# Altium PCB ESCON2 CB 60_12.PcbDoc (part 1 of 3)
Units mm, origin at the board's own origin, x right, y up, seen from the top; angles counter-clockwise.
Board outline 65.5 x 41 mm, 8 copper layers (Top Side, Mid Layer 1, Mid Layer 2, Mid Layer 3, Mid Layer 4, Mid Layer 5, Mid Layer 6, Bottom Side), stack 1.555 mm thick; 142 components, 77 nets, 455 pads, 2194 vias.
Unrouted connection lines stored in the file: 71.
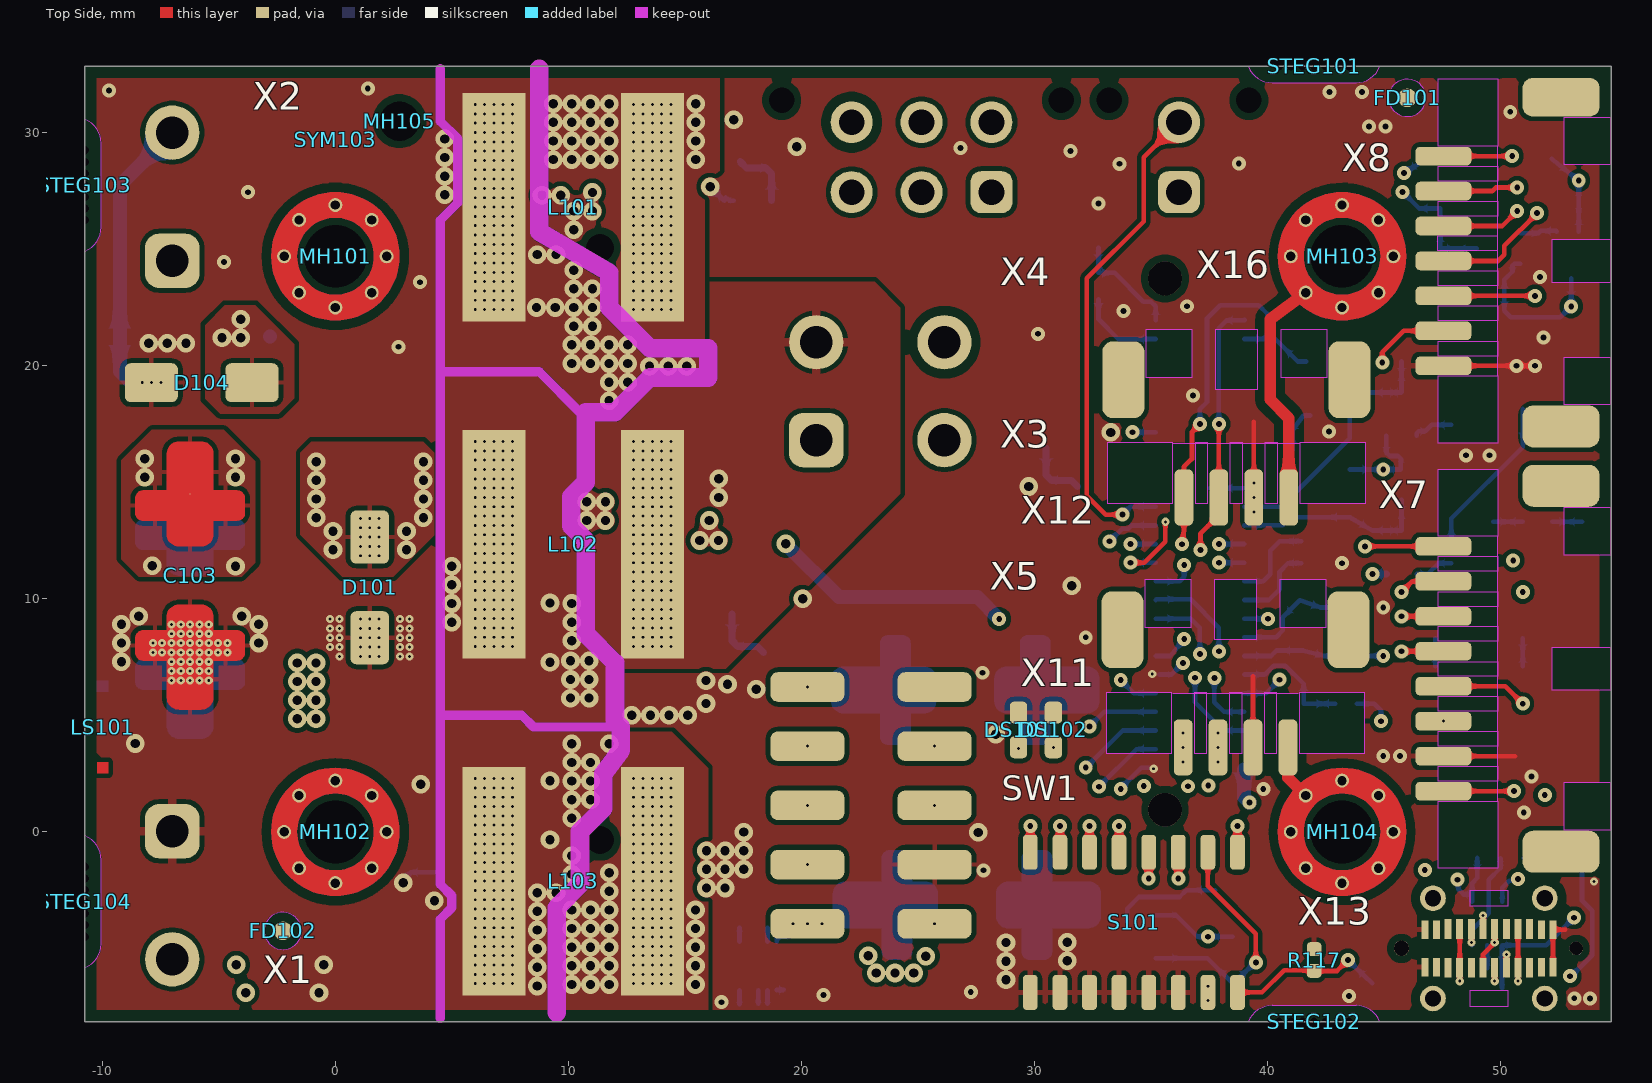
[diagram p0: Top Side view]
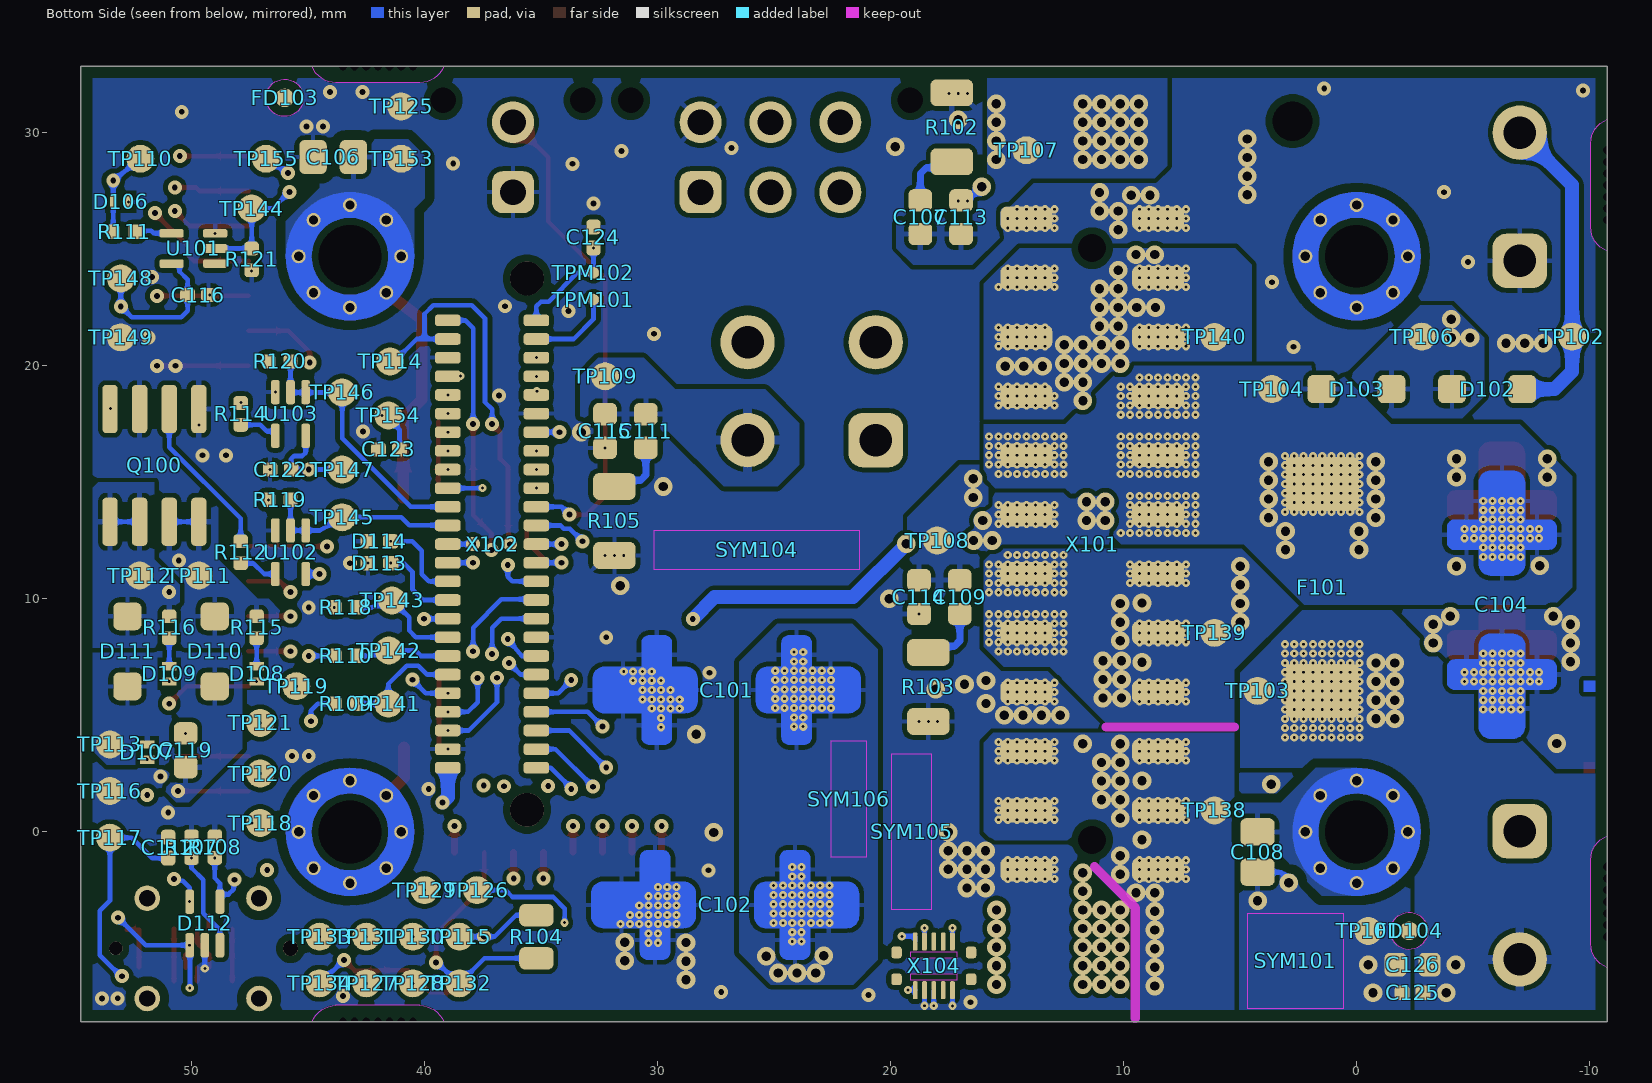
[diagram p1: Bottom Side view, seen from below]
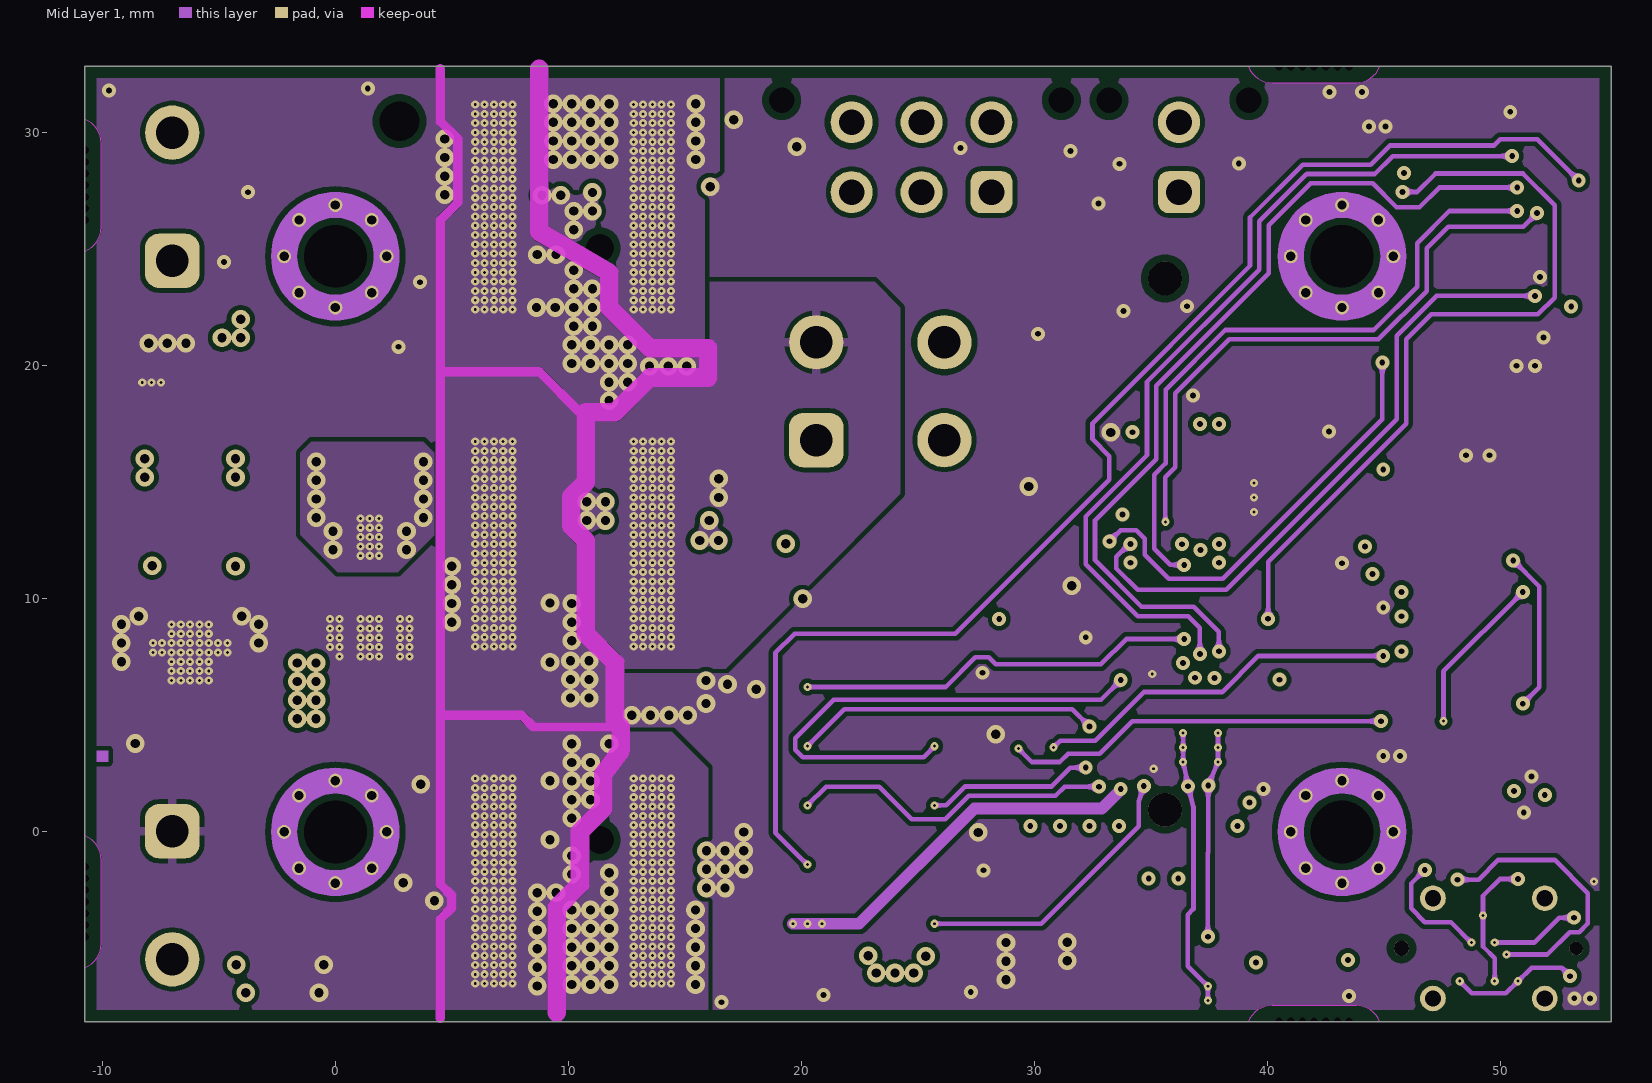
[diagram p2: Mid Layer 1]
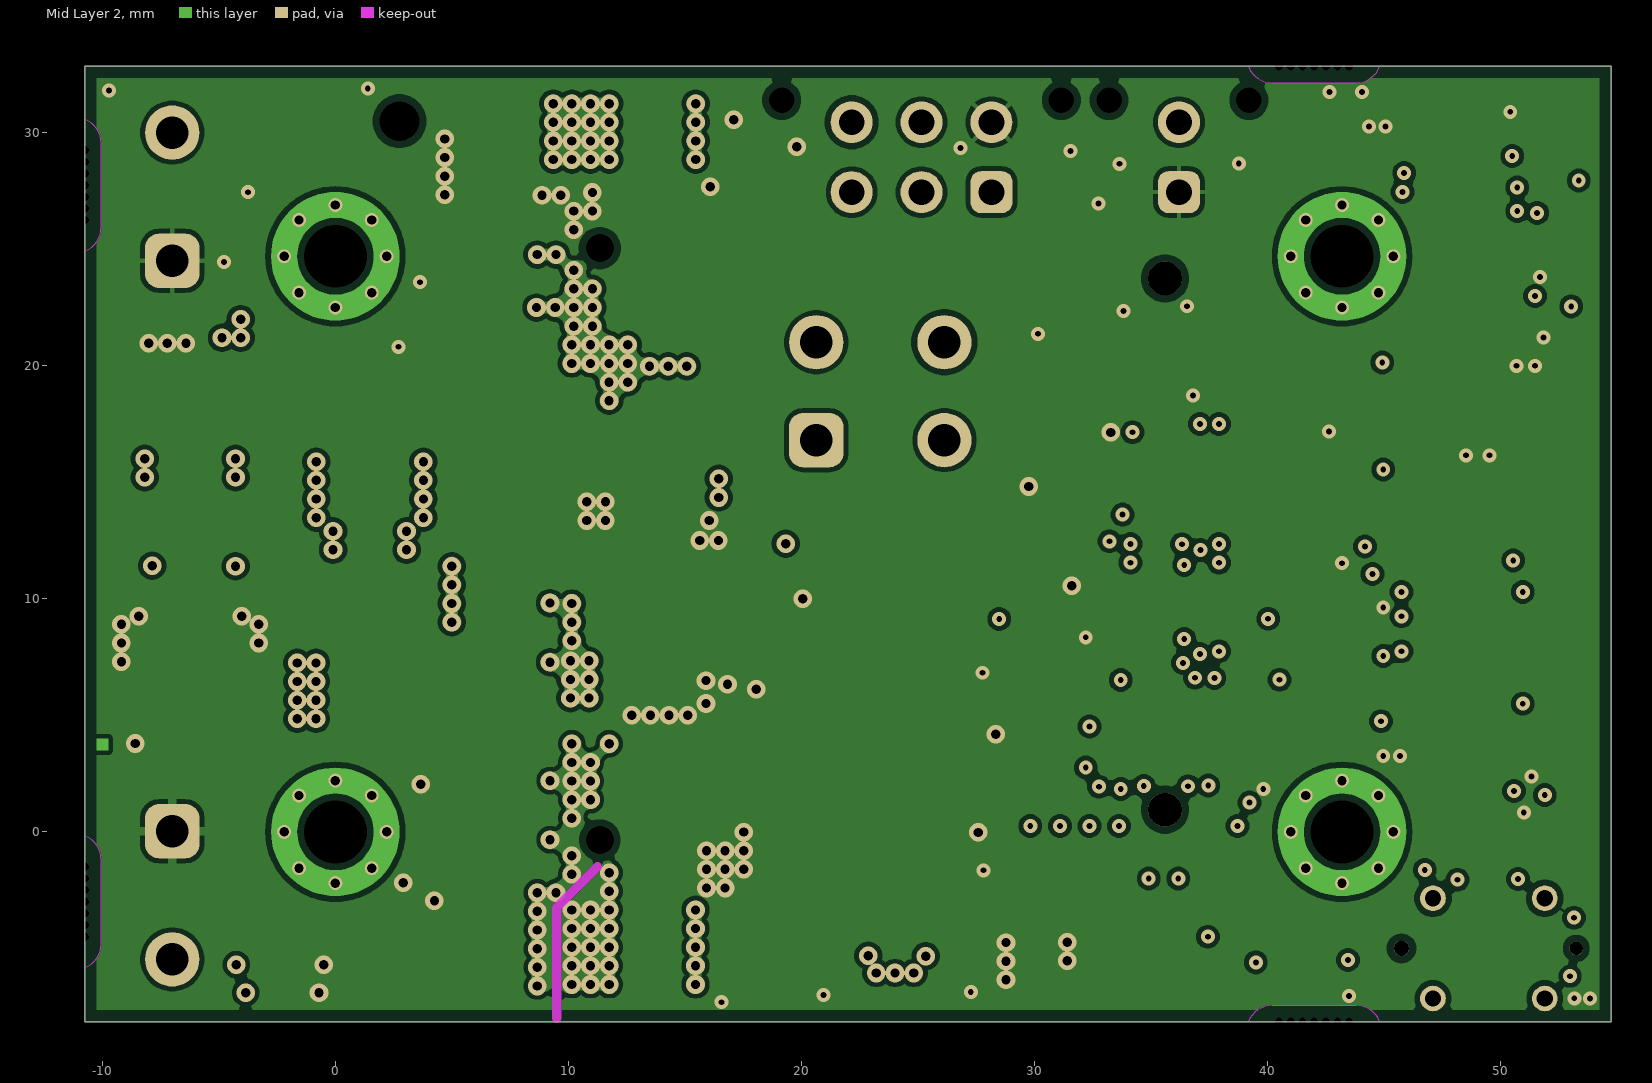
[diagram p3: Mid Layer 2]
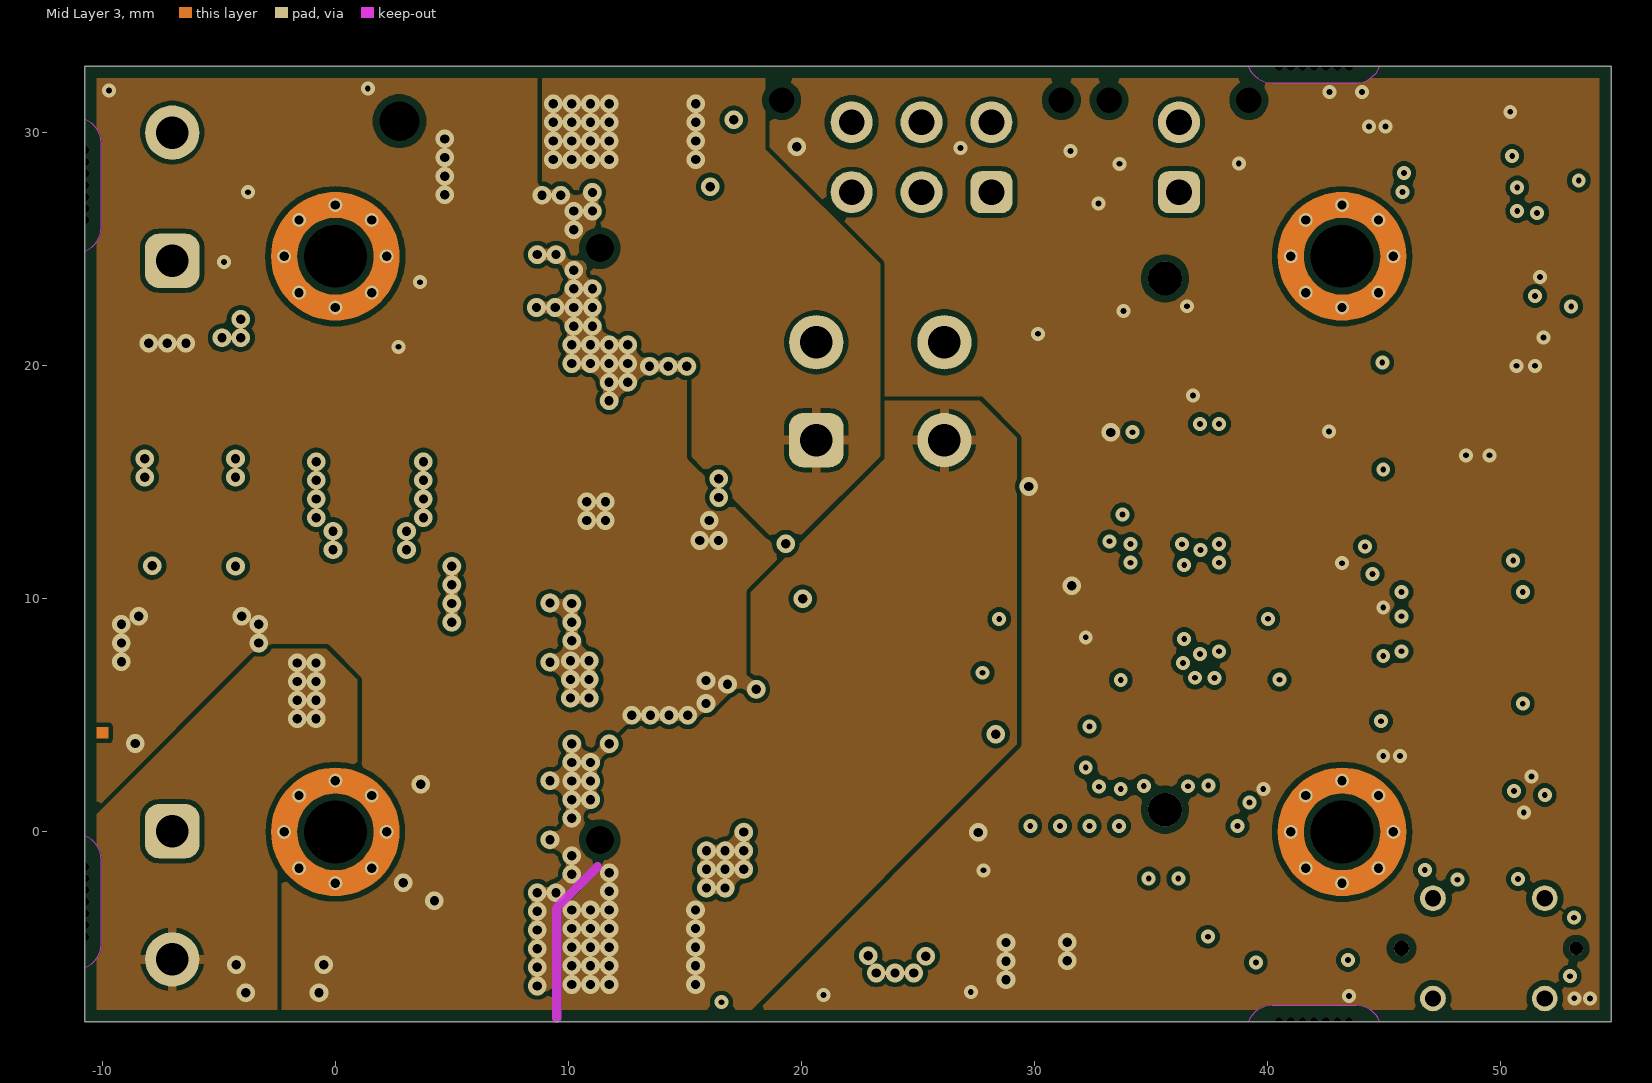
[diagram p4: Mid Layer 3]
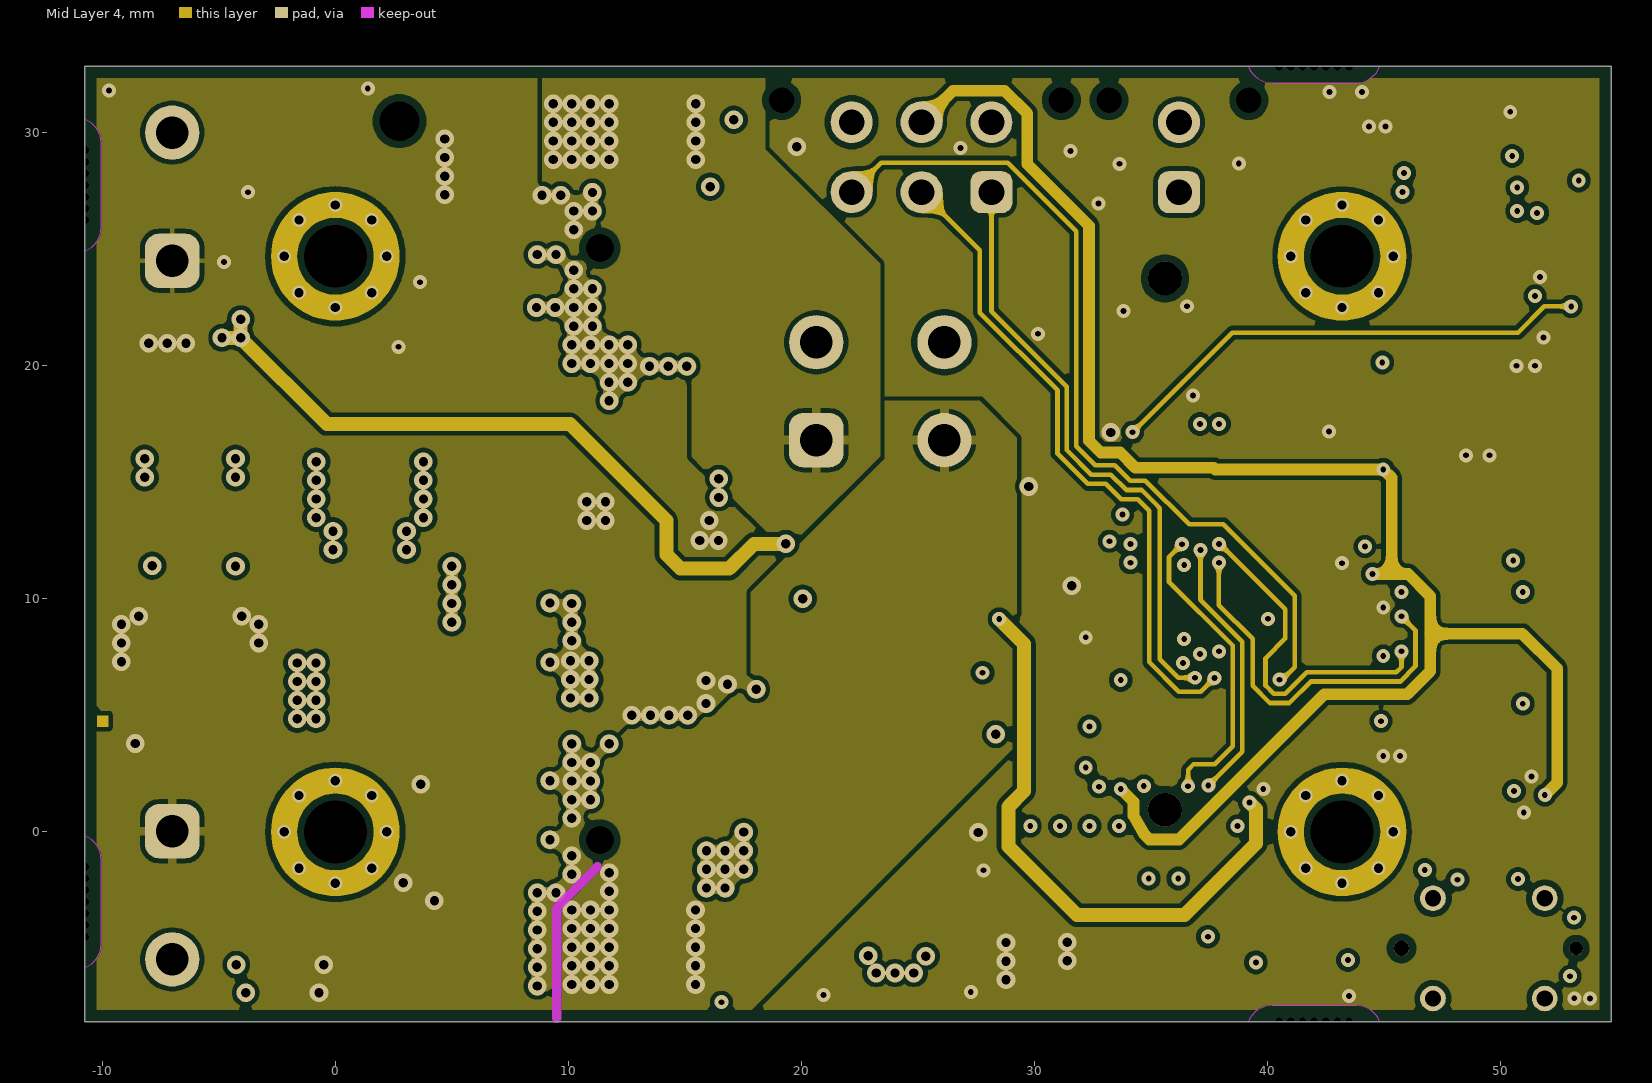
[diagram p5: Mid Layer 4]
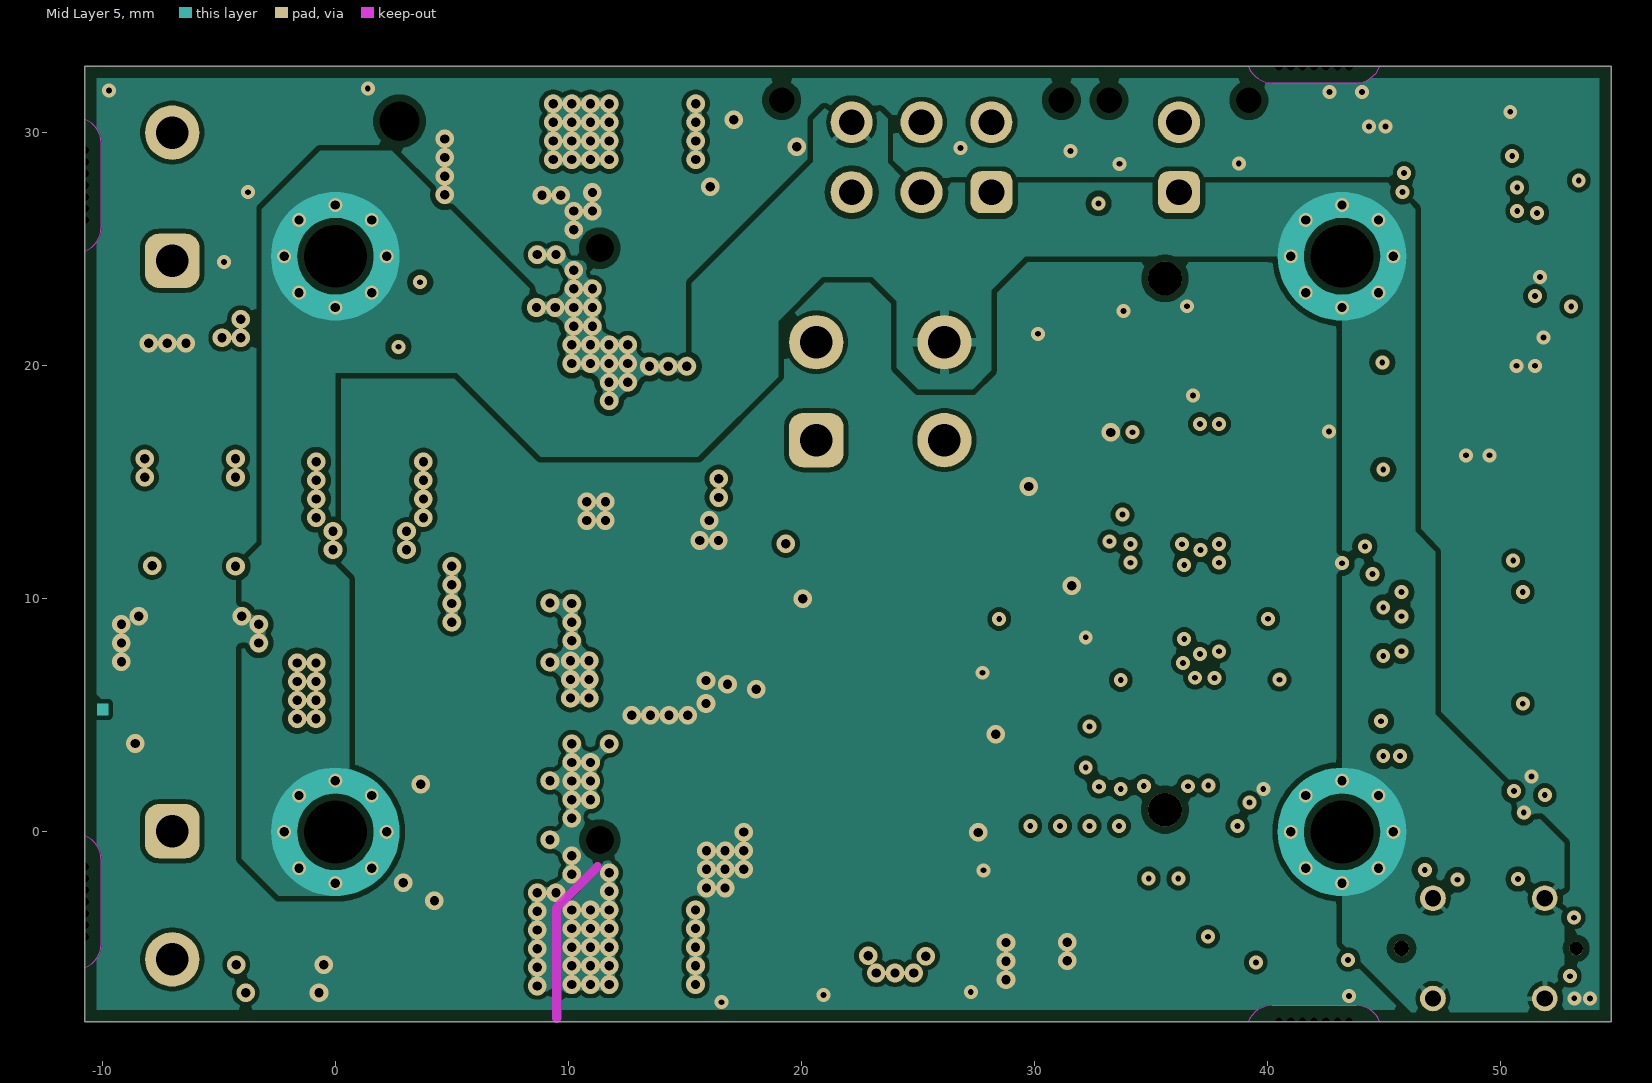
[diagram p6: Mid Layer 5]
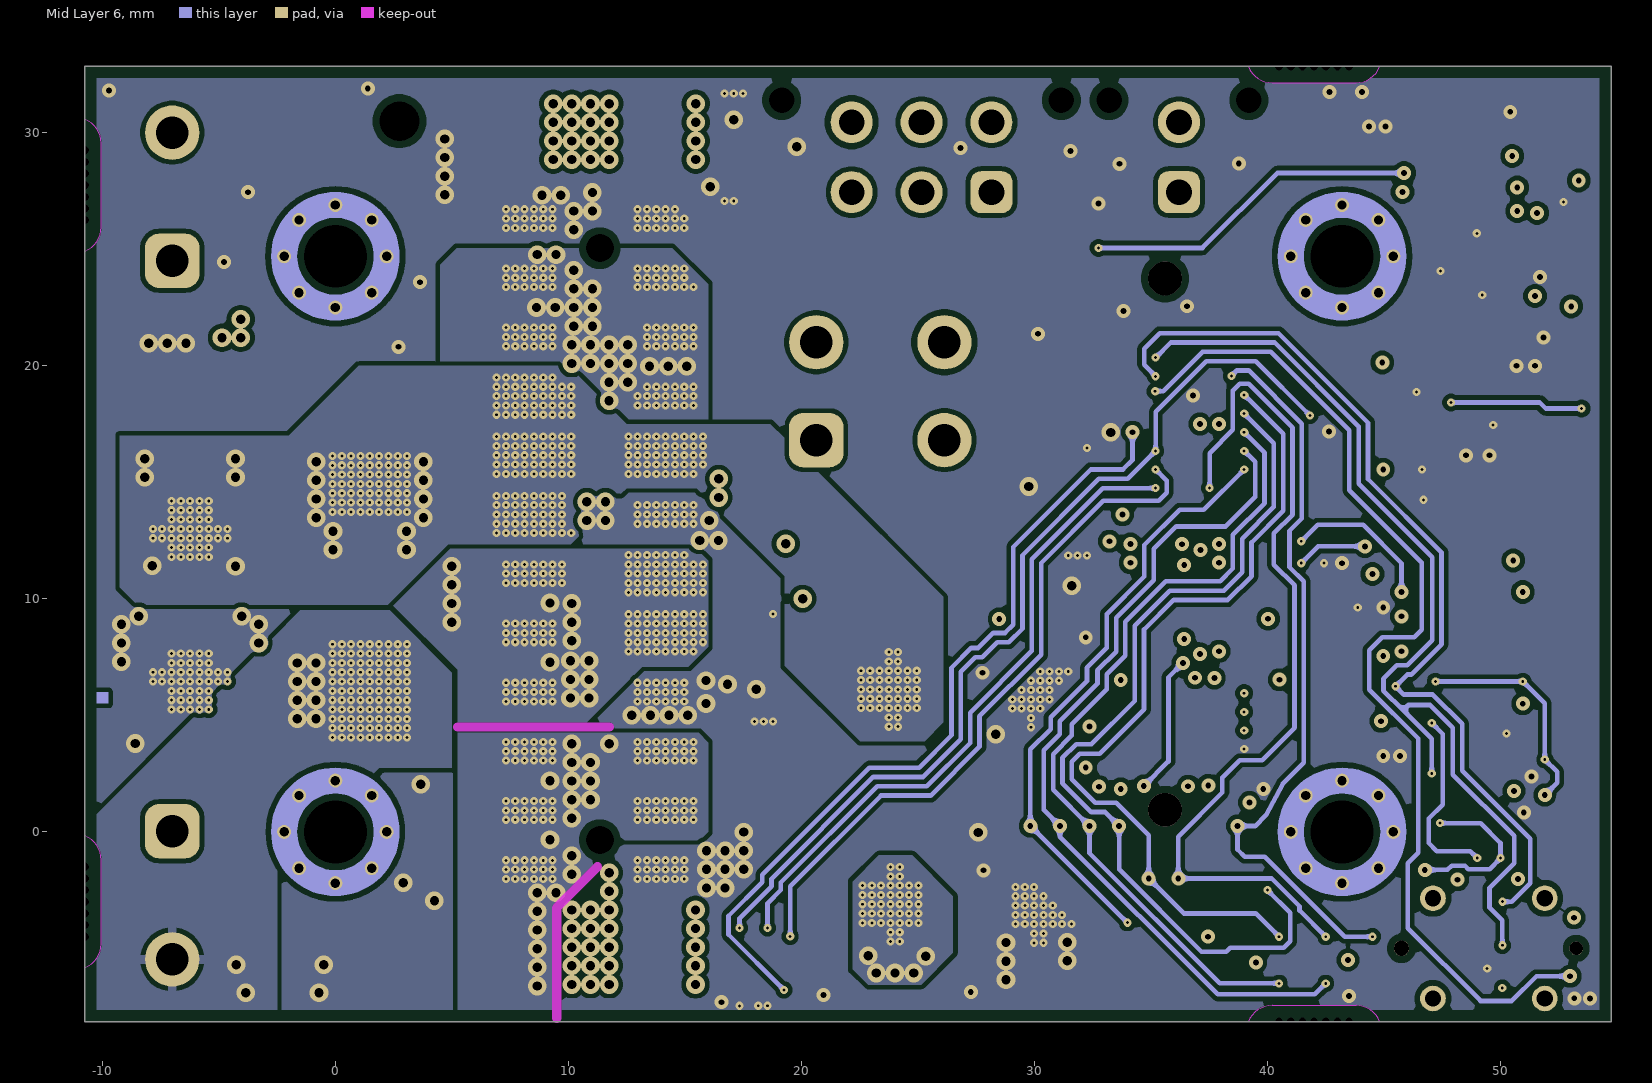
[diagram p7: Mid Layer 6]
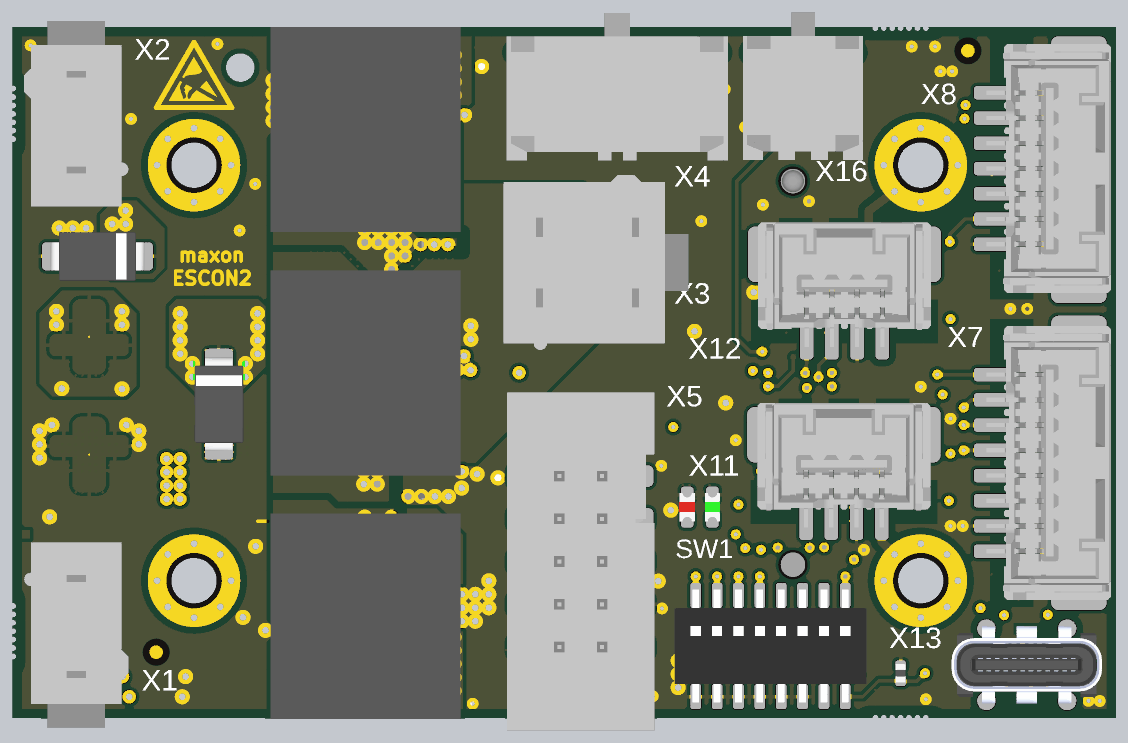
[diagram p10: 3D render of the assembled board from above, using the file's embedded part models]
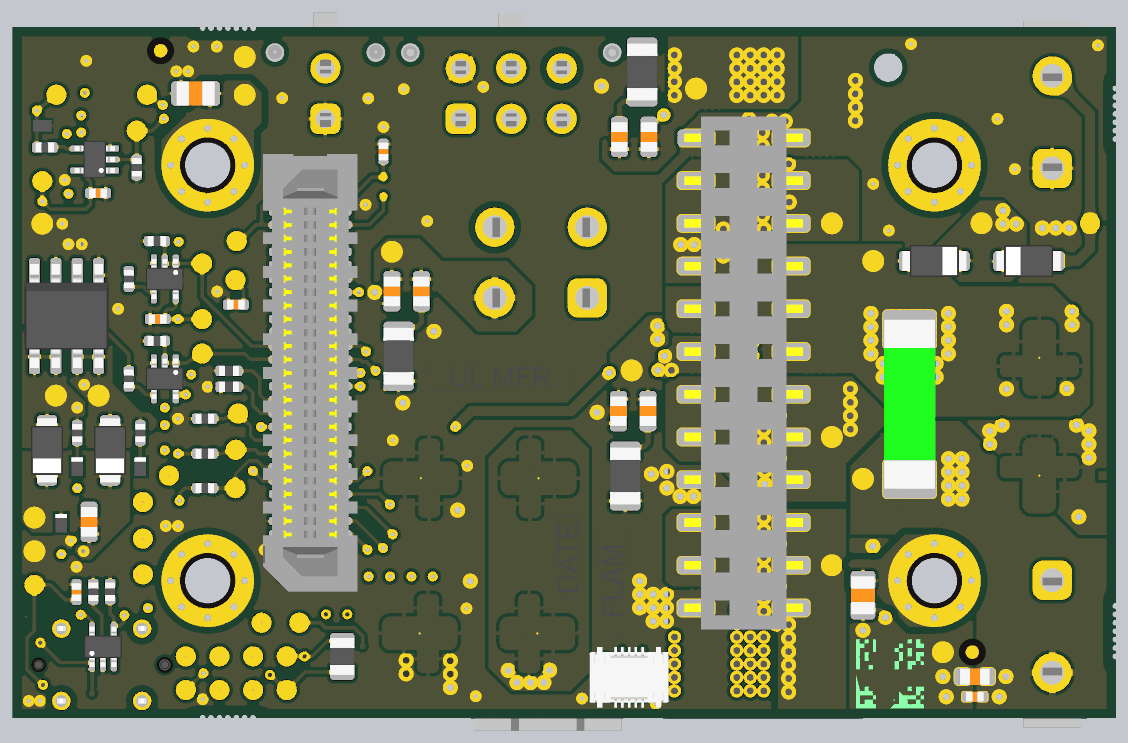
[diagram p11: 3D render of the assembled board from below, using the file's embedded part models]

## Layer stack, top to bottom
Top Solder: solder mask 0.015, Dk 3.5
Top Side: signal copper 0.03
Dielectric 1: prepreg 0.065, Dk 3.5
Mid Layer 1: signal copper 0.035
Core 1: core 0.3, Dk 4.5
Mid Layer 2: signal copper 0.035
Dielectric 2: prepreg 0.125, Dk 3.7
Mid Layer 3: signal copper 0.035
Core 2: core 0.3, Dk 4.5
Mid Layer 4: signal copper 0.035
Dielectric 3: prepreg 0.125, Dk 3.7
Mid Layer 5: signal copper 0.035
Core 3: core 0.3, Dk 4.5
Mid Layer 6: signal copper 0.035
Dielectric 4: prepreg 0.065, Dk 3.5
Bottom Side: signal copper 0.035
Bottom Solder: solder mask 0.015, Dk 3.5

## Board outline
-10.75,-8.15 54.75,-8.15 54.75,32.85 -10.75,32.85

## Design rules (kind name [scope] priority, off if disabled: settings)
AssemblyTestPointUsage [All] p1: valid=2
AssemblyTestpoint [All] p1: testpointundercomponent=TRUE minsize=1 maxsize=2 preferedsize=1.2 minholesize=0 maxholesize=0 preferedholesize=0 testpointgrid=0.05 usegrid=FALSE gridoriginx=120 gridoriginy=100 gridtolerance=0 allowsidebottom=TRUE minspacing=2 padholecenterclearance=0.6
BoardOutlineClearance BOC_AlignHole [InComponent('MH105')] p1: gap=0 ignorepadtopadclearanceinfootprint=FALSE
BoardOutlineClearance BOC_Overlay [OnLayer('Top Designator') OR OnLayer('Bottom Designator')] p2: gap=0 ignorepadtopadclearanceinfootprint=FALSE
BoardOutlineClearance BOC_Text [isText] p3: gap=0 ignorepadtopadclearanceinfootprint=FALSE
BoardOutlineClearance BOC_Fiducials [InComponent('FD*')] p4: gap=0.1 ignorepadtopadclearanceinfootprint=FALSE
BoardOutlineClearance BOC_Steg [InComponent('STEG*')] p5: gap=0 ignorepadtopadclearanceinfootprint=FALSE
BoardOutlineClearance BOC_Keepout [IsKeepout] p6: gap=0 ignorepadtopadclearanceinfootprint=FALSE
BoardOutlineClearance BOC_SGND [InNet('SGND')] p7: gap=0.4 ignorepadtopadclearanceinfootprint=FALSE
BoardOutlineClearance BOC_All [All] p8: gap=0.5 ignorepadtopadclearanceinfootprint=FALSE
Clearance C_NPTHtoAll [(ObjectKind = 'Pad') AND (Layer = 'MultiLayer') AND (PadIsPlated = 'False') AND NOT HasFootprint('Steg*')] p1: gap=0.3 ignorepadtopadclearanceinfootprint=FALSE except(0.298: SMDPad-THPad SMDPad-Fill SMDPad-Poly SMDPad-Region SMDPad-Hole THPad-Fill THPad-Poly THPad-Region Fill-Hole Poly-Hole Region-Hole)
Clearance C_LStoAll [InComponent('LS*')] p2: gap=0.2 ignorepadtopadclearanceinfootprint=FALSE
Clearance C_IsKeepout [IsKeepOut] p3: gap=0 ignorepadtopadclearanceinfootprint=FALSE
Clearance C_NetSGNDtoAll_onOutside [InNet('SGND') AND ( ExistsOnLayer('Top Side') OR ExistsOnLayer('Bottom Side') ) vs (ExistsOnLayer('Top Side') OR ExistsOnLayer('Bottom Side') ) AND NOT IsKeepOut] p4: gap=0.4 ignorepadtopadclearanceinfootprint=FALSE
Clearance C_NetSGNDtoAll_onMid [InNet('SGND') AND ( ExistsOnLayer('Mid Layer 1') OR ExistsOnLayer('Mid Layer 2') OR ExistsOnLayer('Mid Layer 3') OR ExistsOnLayer('Mid Layer 4') OR ExistsOnLayer('Mid Layer 5') OR ExistsOnLayer('Mid Layer 6') OR ExistsOnLayer('Mid Layer 7') OR ExistsOnLayer('Mid Layer 8') OR ExistsOnLayer('Mid Layer 9') OR ExistsOnLayer('Mid Layer 10') ) vs ExistsOnLayer('Mid Layer 1') OR ExistsOnLayer('Mid Layer 2') OR ExistsOnLayer('Mid Layer 3') OR ExistsOnLayer('Mid Layer 4') OR ExistsOnLayer('Mid Layer 5') OR ExistsOnLayer('Mid Layer 6') OR ExistsOnLayer('Mid Layer 7') OR ExistsOnLayer('Mid Layer 8') OR ExistsOnLayer('Mid Layer 9') OR ExistsOnLayer('Mid Layer 10')] p5: gap=0.25 ignorepadtopadclearanceinfootprint=FALSE
Clearance C_ClassHVtoAll_onOutside [InNetClass('HV') AND (ExistsOnLayer('Top Side') OR ExistsOnLayer('Bottom Side')) vs ExistsOnLayer('Top Side') OR ExistsOnLayer('Bottom Side')] p6: gap=0.2 ignorepadtopadclearanceinfootprint=FALSE
Clearance C_ClassHVtoAll_onMidNexToOutside_uVia [InNetClass('HV') AND  ( ExistsOnLayer('Mid Layer 1') OR ExistsOnLayer('Mid Layer 10')) vs ExistsOnLayer('Mid Layer 1') OR ExistsOnLayer('Mid Layer 10')] p7: gap=0.2 ignorepadtopadclearanceinfootprint=FALSE
Clearance C_ClassHVtoAll_onMid [InNetClass('HV')  AND ( ExistsOnLayer('Mid Layer 1') OR ExistsOnLayer('Mid Layer 2') OR ExistsOnLayer('Mid Layer 3') OR ExistsOnLayer('Mid Layer 4') OR ExistsOnLayer('Mid Layer 5') OR ExistsOnLayer('Mid Layer 6') OR ExistsOnLayer('Mid Layer 7') OR ExistsOnLayer('Mid Layer 8') OR ExistsOnLayer('Mid Layer 9') OR ExistsOnLayer('Mid Layer 10') ) vs ExistsOnLayer('Mid Layer 1') OR ExistsOnLayer('Mid Layer 2') OR ExistsOnLayer('Mid Layer 3') OR ExistsOnLayer('Mid Layer 4') OR ExistsOnLayer('Mid Layer 5') OR ExistsOnLayer('Mid Layer 6') OR ExistsOnLayer('Mid Layer 7') OR ExistsOnLayer('Mid Layer 8') OR ExistsOnLayer('Mid Layer 9') OR ExistsOnLayer('Mid Layer 10')] p8: gap=0.2 ignorepadtopadclearanceinfootprint=FALSE
Clearance C_RestToAll_onOutside [(ExistsOnLayer('Top Side') OR ExistsOnLayer('Bottom Side')) vs ExistsOnLayer('Top Side') OR ExistsOnLayer('Bottom Side')] p9: gap=0.2 ignorepadtopadclearanceinfootprint=FALSE
Clearance C_RestToAll_onMidNexToOutside_uVia [(ExistsOnLayer('Mid Layer 1') OR ExistsOnLayer('Mid Layer 10')) vs ExistsOnLayer('Mid Layer 1') OR ExistsOnLayer('Mid Layer 10')] p10: gap=0.2 ignorepadtopadclearanceinfootprint=FALSE
Clearance C_RestToAll_onMid [( ExistsOnLayer('Mid Layer 1') OR ExistsOnLayer('Mid Layer 2') OR ExistsOnLayer('Mid Layer 3') OR ExistsOnLayer('Mid Layer 4') OR ExistsOnLayer('Mid Layer 5') OR ExistsOnLayer('Mid Layer 6') OR ExistsOnLayer('Mid Layer 7') OR ExistsOnLayer('Mid Layer 8') OR ExistsOnLayer('Mid Layer 9') OR ExistsOnLayer('Mid Layer 10') ) vs ExistsOnLayer('Mid Layer 1') OR ExistsOnLayer('Mid Layer 2') OR ExistsOnLayer('Mid Layer 3') OR ExistsOnLayer('Mid Layer 4') OR ExistsOnLayer('Mid Layer 5') OR ExistsOnLayer('Mid Layer 6') OR ExistsOnLayer('Mid Layer 7') OR ExistsOnLayer('Mid Layer 8') OR ExistsOnLayer('Mid Layer 9') OR ExistsOnLayer('Mid Layer 10')] p11: gap=0.2 ignorepadtopadclearanceinfootprint=FALSE
Clearance C_STEGKeepout [InComponent('STEG*') vs IsKeepout] p12: gap=0 ignorepadtopadclearanceinfootprint=FALSE
Clearance C_All [All] p13: gap=0.15 ignorepadtopadclearanceinfootprint=FALSE except(0: SMDPad-Hole THPad-Hole Via-Hole Fill-Hole Poly-Hole Region-Hole Text-Hole; 0.3: Arc-Hole Track-Hole)
ComponentClearance CC_TPMToTP [InComponent('TPM*') vs InComponent('TP*')] p1: gap=0 collisioncheckmode=3 verticalgap=0 showdistances=FALSE
ComponentClearance CC_TPMToCMP [InComponent('TPM*') vs InComponent('*')] p2: gap=0.001 collisioncheckmode=3 verticalgap=0 showdistances=FALSE
ComponentClearance CC_BarcodeToAll [(ObjectKind = '3D Body') And (Identifier = 'Barcode')] p3: gap=0 collisioncheckmode=3 verticalgap=0 showdistances=FALSE donotcheckwithout3dbody=TRUE checkcomponentboundary=TRUE
ComponentClearance CC_LabelToAll [(ObjectKind = '3D Body') And (Identifier = 'Label')] p4: gap=0 collisioncheckmode=3 verticalgap=0 showdistances=FALSE donotcheckwithout3dbody=TRUE checkcomponentboundary=TRUE
ComponentClearance CC_Free3DBody [(ObjectKind = '3D Body') and not InComponent('*') vs (ObjectKind = '3D Body') and not InComponent('*')] p5: gap=0 collisioncheckmode=3 verticalgap=0 showdistances=FALSE
ComponentClearance CC_CMPX201toTP [InComponent('X102') vs InComponent('TP*')] p6: gap=0.25 collisioncheckmode=3 verticalgap=0.1 showdistances=FALSE donotcheckwithout3dbody=TRUE checkcomponentboundary=TRUE
ComponentClearance CC_CMP8MMtoTP_onBottom [(Layer = 'Bottom Side') and InComponent('*')  and (AsMM(Height) >= 8.0) vs InComponent('TP*')] p7: gap=4 collisioncheckmode=3 verticalgap=0.1 showdistances=FALSE donotcheckwithout3dbody=TRUE checkcomponentboundary=TRUE
ComponentClearance CC_CMPtoTP [InComponent('*') vs InComponent('TP*')] p8: gap=0.25 collisioncheckmode=3 verticalgap=0.1 showdistances=FALSE donotcheckwithout3dbody=TRUE checkcomponentboundary=TRUE
ComponentClearance CC_AllToAll [All] p9: gap=0.001 collisioncheckmode=3 verticalgap=0 showdistances=FALSE donotcheckwithout3dbody=TRUE checkcomponentboundary=TRUE
DiffPairsRouting DPR_All [InDifferentialPairClass('Diff_Shunt')] p1: maxlimit=0.3 minlimit=0.125 mostfreqgap=0.2 toplayer_minwidth=0.125 toplayer_maxwidth=0.2 toplayer_prefwidth=0.15 midlayer1_mingap=0.2 midlayer1_minwidth=0.2 midlayer1_maxwidth=0.25 midlayer1_prefwidth=0.2 midlayer2_mingap=0.2 midlayer2_minwidth=0.2 midlayer2_maxwidth=0.25 midlayer2_prefwidth=0.2 midlayer3_mingap=0.2 midlayer3_minwidth=0.2 midlayer3_maxwidth=0.25 midlayer3_prefwidth=0.2 midlayer4_mingap=0.2 midlayer4_minwidth=0.2 midlayer4_maxwidth=0.25 midlayer4_prefwidth=0.2 midlayer5_mingap=0.2 midlayer5_minwidth=0.2 midlayer5_maxwidth=0.25 midlayer5_prefwidth=0.2 midlayer6_mingap=0.2 midlayer6_minwidth=0.2 midlayer6_maxwidth=0.25 midlayer6_prefwidth=0.2 bottomlayer_prefgap=0.15 bottomlayer_minwidth=0.125 bottomlayer_maxwidth=0.2 bottomlayer_prefwidth=0.15 maxuncoupledlength=12.7
FabricationTestPointUsage [All] p1: valid=2 allowmultiple=FALSE
FabricationTestpoint [All] p1: side=2 testpointundercomponent=TRUE minsize=1.2 maxsize=1.2 preferedsize=1.2 minholesize=0 maxholesize=10 preferedholesize=1 testpointgrid=0.025 allowsidebottom=TRUE usegrid=FALSE gridtolerance=0
HoleSize HS_All [All] p1: absolutevalues=TRUE maxlimit=5 minlimit=0.125 maxpercent=80.000 minpercent=20.000
HoleToHoleClearance HtHC_MicroToMicro [IsMicroVia vs IsMicroVia] p1: gap=0.2 allowstackedmicrovias=TRUE
HoleToHoleClearance HtHC_MicroToThru [IsMicroVia vs IsThruVia] p2: gap=0.2 allowstackedmicrovias=TRUE
HoleToHoleClearance HtHC_MicroToBuried [IsMicroVia vs isBuriedVia] p3: gap=0.25 allowstackedmicrovias=FALSE
HoleToHoleClearance HtHC_ThruToBuried [IsThruVia vs isBuriedVia] p4: gap=0.4 allowstackedmicrovias=TRUE
HoleToHoleClearance HtHC_STEG [InComponent('STEG*') vs InComponent('STEG*')] p5: gap=0.1 allowstackedmicrovias=TRUE
HoleToHoleClearance HtHC_All [All] p6: gap=0.4 allowstackedmicrovias=TRUE
LayerPairs LP_All [All] p1: enforce=TRUE
MinimumSolderMaskSliver MSMS_All [All] p1: minsoldermaskwidth=0.1
NetAntennae NA_All [All] p1: netantennaetolerance=0
PasteMaskExpansion PME_All [All] p1: expansion=0
PolygonConnect PCS_Testpoint [Testpoint] p1: connectstyle=Direct reliefconductorwidth=0.254 reliefentries=4 polygonreliefangle="90 Angle" airgapwidth=0.254
PolygonConnect PCS_Testpoint_TPM [InComponent('TPM*')] p2: connectstyle=Direct reliefconductorwidth=0.254 reliefentries=4 polygonreliefangle="90 Angle" airgapwidth=0.254
PolygonConnect PCS_MountingHole [(InComponent('MH*'))] p3: connectstyle=Direct reliefconductorwidth=0.254 reliefentries=4 polygonreliefangle="90 Angle" airgapwidth=0.254
PolygonConnect PCS_DefaultComponents [InComponent('*')] p4: connectstyle=Relief reliefconductorwidth=0.2 reliefentries=4 polygonreliefangle="90 Angle" conductorbypadedge=TRUE mindistance=0.6 enablemindistance=TRUE airgapwidth=0.2
PolygonConnect PCS_All [All] p5: connectstyle=Direct reliefconductorwidth=0.254 reliefentries=4 polygonreliefangle="90 Angle" airgapwidth=0.254
RoutingLayers RL_All [All] p1: top layer_v5=TRUE mid layer 1_v5=TRUE mid layer 2_v5=TRUE mid layer 3_v5=TRUE mid layer 4_v5=TRUE mid layer 5_v5=TRUE mid layer 6_v5=TRUE bottom layer_v5=TRUE
RoutingTopology RT_All [All] p1: topology=Shortest
RoutingVias RVS_MicroVia [IsMicroVia] p1: holewidth=0.125 width=0.35 viastyle="Through Hole" minholewidth=0.125 minwidth=0.35 maxholewidth=0.125 maxwidth=0.35
RoutingVias RVS_SkipVia [IsSkipVia] p2: holewidth=2 width=2 viastyle="Through Hole" minholewidth=2 minwidth=2 maxholewidth=2 maxwidth=2
RoutingVias RVS_BlindVia [IsBlindVia] p3: holewidth=2 width=2 viastyle="Through Hole" minholewidth=2 minwidth=2 maxholewidth=2 maxwidth=2
RoutingVias RVS_BuriedVia [IsBuriedVia] p4: holewidth=0.25 width=0.6 viastyle="Through Hole" minholewidth=0.25 minwidth=0.6 maxholewidth=0.25 maxwidth=0.6
RoutingVias RVS_ThruVia [IsThruVia] p5: holewidth=0.25 width=0.6 viastyle="Through Hole" minholewidth=0.25 minwidth=0.6 maxholewidth=0.4 maxwidth=0.8 useviatemplates=TRUE viatemplateguid#1={CECD491E-926F-4B31-8266-EA1DBC672E18} viatemplateguid#2={D0576803-E7B2-4716-A9E7-9A44D79AEEEE} viatemplatename#1=v60h25m0mx0 viatemplatename#2=v80h40m0mx0
SMDEntry SE_All [All] p1: side=TRUE corner=TRUE anyangle=TRUE
ShortCircuit S-C_All [All] p1: allowed=FALSE
SilkToSilkClearance StSC_All [All] p1: silktosilkclearance=0.25
SilkToSolderMaskClearance StSMC_Pad [All] p1: minsilkscreentomaskgap=0.25 clearancetoexposedcopper=TRUE
SolderMaskExpansion SME_MicroVia [IsMicroVia] p1: expansion=0 istentingtop=TRUE soldermaskfromhole=TRUE
SolderMaskExpansion SME_BlindVia [IsBlindVia] p2: expansion=0 istentingtop=TRUE soldermaskfromhole=TRUE
SolderMaskExpansion SME_ThruVia [IsThruVia] p3: expansion=0.075 istentingtop=FALSE soldermaskfromhole=TRUE
SolderMaskExpansion SME_NPTH [(ObjectKind = 'Pad') AND (Layer = 'MultiLayer') AND (PadIsPlated = 'False')] p4: expansion=0.075 istentingtop=FALSE soldermaskfromhole=TRUE
SolderMaskExpansion SME_Check [All] p5 off: expansion=0.05 istentingtop=FALSE
SolderMaskExpansion SME_All [All] p6: expansion=0 istentingtop=FALSE
SupplyNets "Schematic Supply Nets_8" [InNet('3V3')] p1: voltage=0.000
SupplyNets "Schematic Supply Nets_7" [InNet('5V0_sensor1_2')] p2: voltage=0.000
SupplyNets "Schematic Supply Nets_6" [InNet('C_VDigIO')] p3: voltage=0.000
SupplyNets "Schematic Supply Nets_5" [InNet('C_VL')] p4: voltage=0.000
SupplyNets "Schematic Supply Nets_4" [InNet('VL')] p5: voltage=0.000
SupplyNets "Schematic Supply Nets_3" [InNet('C_VP')] p6: voltage=0.000
SupplyNets "Schematic Supply Nets_2" [InNet('GND')] p7: voltage=0.000
SupplyNets "Schematic Supply Nets_1" [InNet('SGND')] p8: voltage=0.000
SupplyNets "Schematic Supply Nets" [InNet('VP')] p9: voltage=0.000
UnRoutedNet URN_All [All] p1: checkbadconnections=TRUE
UnpouredPolygon MP_All [All] p1:
Width W_onOutside [ExistsOnLayer('Top Side') OR ExistsOnLayer('Bottom Side')] p1: maxlimit=0.6 minlimit=0.2 preferedwidth=0.2 checkconnectedcopper=TRUE
Width W_onMid [ExistsOnLayer('Mid Layer 1') OR ExistsOnLayer('Mid Layer 2') OR ExistsOnLayer('Mid Layer 3') OR ExistsOnLayer('Mid Layer 4') OR ExistsOnLayer('Mid Layer 5') OR ExistsOnLayer('Mid Layer 6') OR ExistsOnLayer('Mid Layer 7') OR ExistsOnLayer('Mid Layer 8') OR ExistsOnLayer('Mid Layer 9') OR ExistsOnLayer('Mid Layer 10')] p2: maxlimit=0.6 minlimit=0.2 preferedwidth=0.2 checkconnectedcopper=TRUE
11 further rules are at their usual default settings.

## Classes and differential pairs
net class HV: C_VL C_VP C_W1 C_W2 C_W3 NetC107_1 NetC109_1 NetC111_1 U V VL VP W

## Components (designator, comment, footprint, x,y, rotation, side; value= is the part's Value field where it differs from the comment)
C101 "EEHZA1K220P" PANASONIC_F_VIB 27.033,6.088 r0 bottom locked value=22µF
C102 "EEHZA1K220P" PANASONIC_F_VIB 27.103,-3.134 r0 bottom locked value=22µF
C103 "EEHZA1K220P" PANASONIC_F_VIB -6.233,11 r270 top locked value=22µF
C104 "EEHZA1K220P" PANASONIC_F_VIB -6.233,9.75 r270 bottom locked value=22µF
C106 "C0805C103KBRACAUTO" CAPC200X125X150L47N 43.919,28.96 r180 bottom value=10nF
C107 "0603 470p" CAPC160X80X100L35N 18.724,26.379 r270 bottom value=470pF
C108 "C0805C103KBRACAUTO" CAPC200X125X150L47N 4.25,-0.865 r90 bottom value=10nF
C109 "0603 470p" CAPC160X80X100L35N 17.03,10.077 r90 bottom value=470pF
C111 "0603 470p" CAPC160X80X100L35N 30.501,17.201 r90 bottom value=470pF
C112 "0402 100nF" CAPC100X50X70L25N 51,-0.674 r270 bottom value=100nF
C113 "0603 220pF" CAPC160X80X100L35N 16.974,26.379 r270 bottom value=220pF
C114 "0603 220pF" CAPC160X80X100L35N 18.78,10.077 r90 bottom value=220pF
C115 "0603 220pF" CAPC160X80X100L35N 32.251,17.201 r90 bottom value=220pF
C116 "0402 100nF" CAPC100X50X70L25N 49.717,23.036 r0 bottom value=100nF
C119 "0603 100nF" CAPC160X80X100L35N 50.25,3.5 r270 bottom value=100nF
C122 "0402 100nF" CAPC100X50X70L25N 46.175,15.55 r180 bottom value=100nF
C123 "0402 100nF" CAPC100X50X70L25N 41.525,16.409 r180 bottom value=100nF
C124 "0402 100nF" CAPC100X50X70L25N 32.751,25.509 r270 bottom value=100nF
C125 "0402 1nF" CAPC100X50X70L25N -2.4,-6.9 r180 bottom value=1nF
C126 "0603 100nF" CAPC160X80X100L35N -2.4,-5.7 r0 bottom value=100nF
D101 "SMAJ60A" DIOM519X260X262L114X145N 1.476,10.49 r270 top
D102 "SS110LW" SODFL359X170X143L65X95N -5.597,19 r180 bottom
D103 "SS110LW" SODFL359X170X143L65X95N 0.005,19 r0 bottom
D104 "SMAJ60A" DIOM519X260X262L114X145N -5.74,19.278 r180 top
D106 "D12V0L1B2LP-7B" DIONPDFN2_102X60X60L25X50N 53.032,27.036 r0 bottom
D107 "1N4148WL2-TP" DIODFN2_102X60X60L25X50N 51.9,3.425 r270 bottom
D108 "1N4148WL2-TP" DIODFN2_102X60X60L25X50N 47.205,6.78 r270 bottom
D109 "1N4148WL2-TP" DIODFN2_102X60X60L25X50N 50.955,6.78 r270 bottom
D110 "SS110LW" SODFL359X170X143L65X95N 49,7.745 r90 bottom
D111 "SS110LW" SODFL359X170X143L65X95N 52.75,7.745 r90 bottom
D112 "PESD5V0L4UG" SOT23-5P65_210X110L28X20N 49.429,-3.932 r180 bottom
D113 "EZAEG2A50AX" DIONPC105X53X43L26N 41.935,11.53 r180 bottom
D114 "EZAEG2A50AX" DIONPC105X53X43L26N 41.935,12.47 r180 bottom
DS101 "598-8010-107F" LEDSC80X160X90L45N_RED 29.315,4.374 r270 top
DS102 "598-8070-107F" LEDSC80X160X90L45N_GREEN 30.815,4.374 r270 top
F101 "0456020." FUSC1008X305X305L170N 1.476,10.49 r90 bottom
FD101 "FDc80c160" FIDUCIAL_c80_c160 46,31.5 r0 top locked
FD102 "FDc80c160" FIDUCIAL_c80_c160 -2.25,-4.25 r0 top locked
FD103 "FDc80c160" FIDUCIAL_c80_c160 46,31.5 r180 bottom locked
FD104 "FDc80c160" FIDUCIAL_c80_c160 -2.25,-4.25 r0 bottom locked
L101 "EXL1V1010-4R7-R" INDDFN2_1040X1150X1000L235X930N 10.202,26.813 r180 top locked value=4.7µH
L102 "EXL1V1010-4R7-R" INDDFN2_1040X1150X1000L235X930N 10.202,12.35 r180 top locked value=4.7µH
L103 "EXL1V1010-4R7-R" INDDFN2_1040X1150X1000L235X930N 10.202,-2.113 r180 top locked value=4.7µH
LS101 "LAYERSTAIR 8 LAYER" 8LS400X50w/oLETTERS_KEEPOUT -9.99,4.5 r90 top
MH101 "MTGNPH270A550V8H40" MTGNPH270A550V8H40 0,24.7 r0 top locked
MH102 "MTGNPH270A550V8H40" MTGNPH270A550V8H40 0,0 r0 top locked
MH103 "MTGNPH270A550V8H40" MTGNPH270A550V8H40 43.2,24.7 r0 top locked
MH104 "MTGNPH270A550V8H40" MTGNPH270A550V8H40 43.2,0 r0 top locked
MH105 "MTGNPH170_NPTH" MTGNPH170 2.75,30.5 r0 top locked
Q100 "VNS1NV04DP-E" SOIC8P127_490X599X175L83X41N 51.59,15.728 r0 bottom
R102 "1206 56R" RESC320X160X90L47N 17.374,30.238 r270 bottom value=56
R103 "1206 56R" RESC320X160X90L47N 18.38,6.218 r90 bottom value=56
R104 "0805 120R" RESC200X125X84L35N 35.2,-4.5 r90 bottom value=120
R105 "1206 56R" RESC320X160X90L47N 31.851,13.342 r90 bottom value=56
R107 "0402 5.1k" RESC100X52X40L22N 50,-0.659 r90 bottom value=5.1k
R108 "0402 5.1k" RESC100X52X40L22N 49,-0.654 r90 bottom value=5.1k
R109 "0402 680R" RESC100X52X40L22N 43.372,5.5 r0 bottom value=680
R110 "0402 680R" RESC100X52X40L22N 43.372,7.55 r0 bottom value=680
R111 "0402 47R" RESC100X52X40L22N 52.887,25.756 r180 bottom value=47
R112 "0402 220R" RESC100X52X40L22N 47.89,12 r90 bottom value=220
R114 "0402 220R" RESC100X52X40L22N 47.89,17.935 r90 bottom value=220
R115 "0402 2.2k" RESC100X52X40L22N 47.205,8.78 r270 bottom value=2.2k
R116 "0402 2.2k" RESC100X52X40L22N 50.955,8.78 r270 bottom value=2.2k
R117 "0402 0" RESC100X52X40L22N 42,-5.5 r270 top value=0
R118 "0402 10k" RESC100X52X40L22N 43.372,9.631 r180 bottom value=10k
R119 "0402 10k" RESC100X52X40L22N 46.22,14.25 r180 bottom value=10k
R120 "0402 10k" RESC100X52X40L22N 46.22,20.185 r180 bottom value=10k
R121 "0402 10k" RESC100X52X40L22N 47.417,24.566 r90 bottom value=10k
S101 "DHN-08F-T-V" SOIC16P127_1139X671X151L61X41N 34.267,-3.882 r0 top locked
STEG101 "Steg570X90_7Hole" Steg_570X90_7Hole 42,32.85 r180 top
STEG102 "Steg570X90_7Hole" Steg_570X90_7Hole 42,-8.15 r0 top
STEG103 "Steg570X90_7Hole" Steg_570X90_7Hole -10.75,27.75 r270 top
STEG104 "Steg570X90_7Hole" Steg_570X90_7Hole -10.75,-3 r270 top
SYM101 "BARCODE_EMS410x410" BARCODE_EMS_410x410 2.625,-5.534 r180 bottom
SYM103 "ESD500X450" ESD_small 0,29.703 r0 top
SYM104 "PCB_MARKING_UL_MANUFACTURER880x170" "UL_MANUFACTURER _MARKING_PCB_880x170" 25.75,12.1 r180 bottom
SYM105 "PCB_MARKING_FLAMMABILITY670x170" FLAMMABILITY_MARKING_PCB_670x170 19.1,0 r90 bottom
SYM106 "PCB_MARKING_DATE500x150" DATE_MARKING_PCB_500x150 21.8,1.4 r90 bottom
TP101 "TPc120" TESTPOINT_c120 -0.5,-4.25 r180 bottom locked
TP102 "TPc120" TESTPOINT_c120 -9.25,21.25 r180 bottom locked
TP103 "TPc120" TESTPOINT_c120 4.25,6.05 r180 bottom locked
TP104 "TPc120" TESTPOINT_c120 3.636,19 r270 bottom locked
TP106 "TPc120" TESTPOINT_c120 -2.796,21.25 r270 bottom locked
TP107 "TPc120" TESTPOINT_c120 14.172,29.25 r180 bottom locked
TP108 "TPc120" TESTPOINT_c120 18,12.5 r180 bottom locked
TP109 "TPc120" TESTPOINT_c120 32.251,19.55 r180 bottom locked
TP110 "TPc120" TESTPOINT_c120 52.194,28.885 r180 bottom locked
TP111 "TPc120" TESTPOINT_c120 49.685,11 r270 bottom locked
TP112 "TPc120" TESTPOINT_c120 52.225,11 r270 bottom locked
TP113 "TPc120" TESTPOINT_c120 53.5,3.75 r90 bottom locked
TP114 "TPc120" TESTPOINT_c120 41.475,20.185 r180 bottom locked
TP115 "TPc120" TESTPOINT_c120 38.5,-4.5 r180 bottom locked
TP116 "TPc120" TESTPOINT_c120 53.5,1.75 r0 bottom locked
TP117 "TPc120" TESTPOINT_c120 53.5,-0.25 r0 bottom locked
TP118 "TPc120" TESTPOINT_c120 47.05,0.376 r0 bottom locked
TP119 "TPc120" TESTPOINT_c120 45.5,6.25 r0 bottom locked
TP120 "TPc120" TESTPOINT_c120 47.05,2.5 r0 bottom locked
TP121 "TPc120" TESTPOINT_c120 47.05,4.675 r0 bottom locked
TP125 "TPc120" TESTPOINT_c120 41,31.132 r180 bottom locked
TP126 "TPc120" TESTPOINT_c120 37.75,-2.5 r0 bottom locked
TP127 "TPc120" TESTPOINT_c120 42.5,-6.5 r0 bottom locked
TP128 "TPc120" TESTPOINT_c120 40.5,-6.5 r0 bottom locked
TP129 "TPc120" TESTPOINT_c120 40,-2.5 r0 bottom locked
TP130 "TPc120" TESTPOINT_c120 40.5,-4.5 r0 bottom locked
TP131 "TPc120" TESTPOINT_c120 42.5,-4.5 r0 bottom locked
TP132 "TPc120" TESTPOINT_c120 38.5,-6.5 r0 bottom locked
TP133 "TPc120" TESTPOINT_c120 44.5,-4.5 r0 bottom locked
TP134 "TPc120" TESTPOINT_c120 44.5,-6.5 r180 bottom locked
TP138 "TPc120" TESTPOINT_c120 6.1,0.92 r180 bottom locked
TP139 "TPc120" TESTPOINT_c120 6.1,8.54 r180 bottom locked
TP140 "TPc120" TESTPOINT_c120 6.1,21.24 r180 bottom locked
TP141 "TPc120" TESTPOINT_c120 41.55,5.5 r180 bottom locked
TP142 "TPc120" TESTPOINT_c120 41.529,7.78 r180 bottom locked
TP143 "TPc120" TESTPOINT_c120 41.39,9.931 r180 bottom locked
TP144 "TPc120" TESTPOINT_c120 47.417,26.75 r180 bottom locked
TP145 "TPc120" TESTPOINT_c120 43.533,13.5 r180 bottom locked
TP146 "TPc120" TESTPOINT_c120 43.533,18.855 r180 bottom locked
TP147 "TPc120" TESTPOINT_c120 43.533,15.55 r180 bottom locked
TP148 "TPc120" TESTPOINT_c120 53.032,23.75 r270 bottom locked
TP149 "TPc120" TESTPOINT_c120 53.032,21.22 r270 bottom locked
TP153 "TPc120" TESTPOINT_c120 41,28.885 r270 bottom locked
TP154 "TPc120" TESTPOINT_c120 41.55,17.868 r90 bottom locked
TP155 "TPc120" TESTPOINT_c120 46.8,28.885 r180 bottom locked
TPM101 "TPMc50" TESTPOINTMEASURE_c50 32.751,22.844 r90 bottom
TPM102 "TPMc50" TESTPOINTMEASURE_c50 32.751,23.988 r90 bottom
U101 "SN74LVC1G17DCK" SOT23-5P65_210X110L28X20N 49.917,25.036 r90 bottom
U102 "SN74AHCT1G00DCKR" SOT23-5P65_210X110L28X20N 45.75,12 r0 bottom
U103 "SN74AHCT1G00DCKR" SOT23-5P65_210X110L28X20N 45.75,17.935 r0 bottom
X1 "460150202" MOLEX_460150202 -7,-2.722 r0 top locked
X2 "460150202" MOLEX_460150202 -7,27.256 r180 top locked
X3 "460150402" MOLEX_460150402 23.186,18.911 r90 top locked
X4 "430450612" "MOLEX_ 430450612" 25.154,28.953 r0 top locked
X5 "52601-S10-8LF" AMPHENOL_52601-S10-8LF 22.988,1.137 r90 top locked
X7 "5025840860" MOLEX_5025840860 51.325,7 r270 top locked
X8 "5025840760" MOLEX_5025840760 51.325,24.5 r270 top locked
X11 "5025840460" MOLEX_5025840460 38.629,7.4 r0 top locked
X12 "5025840460" MOLEX_5025840460 38.665,18.125 r0 top locked
X13 "USB4115-03-C" GTC_USB4115-03-C 49.5,-5 r0 top locked
X16 "430450212" "MOLEX_ 430450212" 36.202,28.953 r0 top locked
X101 "SSM-112-F-DV-A" SAMTEC_SSM-112-L-DV-A 11.35,12.35 r270 bottom locked
X102 "ERM8-025-05.0-L-DV" SAMTEC_ERM8-025-05.0-L-DV 37.1,12.35 r90 bottom locked
X104 "AXT410124" "PANASONIC_AXT410124 (with 3D counterpart)" 18.145,-5.75 r180 bottom

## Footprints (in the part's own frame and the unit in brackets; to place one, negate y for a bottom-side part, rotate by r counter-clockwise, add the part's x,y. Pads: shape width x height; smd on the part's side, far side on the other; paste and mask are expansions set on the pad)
8LS400X50w/oLETTERS_KEEPOUT [mm] "Layerstair 8 Layers, 4.00 mm X 0.5 mm, without Letters and KeepOut"
  Top Side region: -2,-0.25 -1.5,-0.25 -1.5,0.25 -2,0.25
  Mid Layer 1 region: -1.5,-0.25 -1,-0.25 -1,0.25 -1.5,0.25
  Mid Layer 2 region: -1,-0.25 -0.5,-0.25 -0.5,0.25 -1,0.25
  Mid Layer 3 region: -0.5,-0.25 0,-0.25 0,0.25 -0.5,0.25
  Mid Layer 6 region: 1.5,0.25 1,0.25 1,-0.25 1.5,-0.25
  Mid Layer 4 region: 0.5,0.25 0,0.25 0,-0.25 0.5,-0.25
  Mid Layer 5 region: 1,0.25 0.5,0.25 0.5,-0.25 1,-0.25
  Bottom Side region: 1.5,-0.25 2,-0.25 2,0.25 1.5,0.25
AMPHENOL_52601-S10-8LF [mm] "Header, 2.54mm Pitch, Dual Row, SMT, Vertical, 10 Circuits"
  rrect50% 1.27x3.18 smd: 1(-5.08,-2.73) 2(-5.08,2.73) 3(-2.54,-2.73) 4(-2.54,2.73) 5(0,-2.73) 6(0,2.73) 7(2.54,-2.73) 8(2.54,2.73) 9(5.08,-2.73) 10(5.08,2.73)
  body extent -10.05,-4.38 10.05,4.38, height 12.76
BARCODE_EMS_410x410 [mm] "Barcode EMS, 4.10 mm L X 4.10 mm W X 0.00 mm H body"
  Top Side keep-out region: -2.05,2.05 2.05,2.05 2.05,-2.05 -2.05,-2.05
  body extent -2.05,-2.05 2.05,2.05, height 0.01
CAPC100X50X70L25N [mm] "Capacitor, Chip; 1.00 mm L X 0.50 mm W X 0.70 mm H body"
  rrect49% 0.63x0.61 smd: 1(-0.45,0) 2(0.45,0)
  body extent -0.55,-0.3 0.55,0.3, height 0.7
CAPC160X80X100L35N [mm] "Capacitor, Chip; 1.60 mm L X 0.80 mm W X 1.00 mm H body"
  rrect50% 0.96x1.02 smd: 1(-0.725,0) 2(0.725,0)
  body extent -0.9,-0.5 0.9,0.5, height 1
CAPC200X125X150L47N [mm] "Capacitor, Chip; 2.00 mm L X 1.25 mm W X 1.50 mm H body"
  rrect42% 1.18x1.47 smd: 1(-0.865,0) 2(0.865,0)
  body extent -1.15,-0.72 1.15,0.72, height 1.5
DATE_MARKING_PCB_500x150 [mm] "Date Marking PCB, 5.00 mm L X 1.50 mm W X 0.00 mm H body"
  Top Side keep-out region: -2.5,0.749 2.5,0.749 2.5,-0.751 -2.5,-0.751
  body extent -2.5,-0.75 2.5,0.75, height 0.02
DIODFN2_102X60X60L25X50N [mm] "Diode, Dual Flat No-Lead (DFN 2 Pin); 2 pin, 1.025 mm L X 0.60 mm W X 0.60 mm H body"
  rect 0.36x0.63 smd: 1(-0.325,0) 2(0.325,0)
  body extent -0.55,-0.35 0.55,0.35, height 0.6
DIOM519X260X262L114X145N [mm] "Diode, Molded Body; 4.295 mm L X 2.605 mm W X 2.62 mm H body"
  rrect30% 2.277x1.665 smd: 1(-2.16,0) 2(2.16,0)
  body extent -2.8,-1.46 2.8,1.46, height 2.62
DIONPC105X53X43L26N [mm] "Diode, Non-polarized, Chip; 1.05 mm L X 0.53 mm W X 0.43 mm H Body"
  rrect50% 0.65x0.625 smd: 1(-0.485,0) 2(0.485,0)
  body extent -0.6,-0.31 0.6,0.31, height 0.43
DIONPDFN2_102X60X60L25X50N [mm] "Diode, Non-polarized, Dual Flat No-Lead, 2 pin; 1.025 mm L X 0.60 mm W X 0.60 mm H body"
  rect 0.28x0.549 smd: 1(-0.325,0) 2(0.325,0)
  body extent -0.55,-0.35 0.55,0.35, height 0.6
ESD_small [mm] "ESD-Sign soldermask 5.0x4.5mm"
FIDUCIAL_c80_c160 [mm] "Fiducial, Global; 0 pin"
  round 0.8 smd paste-0.8 mask+0.4: 1(0,0)
  Top Side keep-out circle w0.025: c0,0 r0.8
FLAMMABILITY_MARKING_PCB_670x170 [mm] "Flammability Marking PCB, 6.70 mm L X 1.70 mm W X 0.00 mm H body"
  Top Side keep-out region: -3.35,0.85 3.35,0.85 3.35,-0.85 -3.35,-0.85
  body extent -3.35,-0.85 3.35,0.85, height 0.02
FUSC1008X305X305L170N [mm] "Fuse, Chip; 10.08 mm L X 3.05 mm W X 3.05 mm H Body"
  rrect22% 2.311x3.162 smd: 1(-4.44,0) 2(4.44,0)
  body extent -5.04,-1.53 5.04,1.53, height 3.05
GTC_USB4115-03-C [mm] "USB Type C, SHLD, 24poles"
  round 0.66 hole 0.66 unplated mask+0.15: 0(-3.75,0)
  round 0.58 hole 0.58 unplated mask+0.15: 0(3.75,0)
  rect 0.3x0.79 smd: A1(-2.75,0.805) A2(-2.25,0.805) A11(2.25,0.805) A12(2.75,0.805) B1(2.75,-0.805) B2(2.25,-0.805) B11(-2.25,-0.805) B12(-2.75,-0.805)
  rect 0.3x0.85 smd: A3(-1.75,0.835) A4(-1.25,0.835) A5(-0.75,0.835) A6(-0.25,0.835) A7(0.25,0.835) A8(0.75,0.835) A9(1.25,0.835) A10(1.75,0.835) B3(1.75,-0.835) B4(1.25,-0.835) B5(0.75,-0.835) B6(0.25,-0.835) B7(-0.25,-0.835) B8(-0.75,-0.835) B9(-1.25,-0.835) B10(-1.75,-0.835)
  round 1.1 hole 0.7: S1(-2.4,2.15) S2(-2.4,-2.15) S3(2.4,-2.15) S4(2.4,2.15)
  Top Side keep-out region: 0.8,-2.5 -0.8,-2.5 -0.8,-1.8 0.8,-1.8
  Top Side keep-out region: 0.8,1.8 -0.8,1.8 -0.8,2.5 0.8,2.5
  body extent -4.47,-2.3 4.47,2.3, height 9.25
INDDFN2_1040X1150X1000L235X930N [mm] "Inductor, Dual Flat No-Lead (DFN) 2 pins; 10.40 mm L X 11.50 mm W X 10.00 mm H body"
  rect 2.701x9.806 smd: 1(-3.4,0) 2(3.4,0)
  body extent -5.65,-6.1 5.65,6.1, height 10
LEDSC80X160X90L45N_GREEN [mm] "LED, Side Concave Package; 2 pin, 0.80 mm L X 1.60 mm W X 0.90 mm H body, green"
  rrect50% 0.94x0.749 smd: 1(-0.745,0) 2(0.745,0)
  body extent -0.85,-0.45 0.85,0.45, height 0.9
LEDSC80X160X90L45N_RED [mm] "LED, Side Concave Package; 2 pin, 0.80 mm L X 1.60 mm W X 0.90 mm H body, red"
  rrect50% 0.94x0.749 smd: 1(-0.745,0) 2(0.745,0)
  body extent -0.85,-0.45 0.85,0.45, height 0.9
MOLEX_460150202 [mm] "Header, Vertical Shrouded, 4.20 mm row X 5.50 mm column pitch; 1.00 mm lead width, 2 pins, 2 rows, 1 pin per row, 5.40 mm L X 9.60 mm W X 12.80 mm H body"
  rrect50% 2.33x2.33 hole 1.4: 1(0,2.75)
  round 2.33 hole 1.4: 2(0,-2.75)
  body extent -3.1,-6 3.1,5, height 12.81
MOLEX_460150402 [mm] "Header, Vertical Shrouded, 4.20 mm row X 5.50 mm column pitch; 1.00 mm lead width, 4 pins, 2 rows, 2 pins per row, 9.60 mm L X 9.60 mm W X 12.80 mm H body"
  rrect50% 2.33x2.33 hole 1.4: 1(-2.1,2.55)
  round 2.33 hole 1.4: 2(2.1,2.55) 3(-2.1,-2.95) 4(2.1,-2.95)
  body extent -5.2,-6.2 5.2,4.8, height 12.8
MOLEX_5025840460 [mm] "Header, 1.5mm pitch, 4 position, top entry, SMT"
  rrect50% 1.8x3.3 smd: 0(-4.85,1.275) 0(4.85,1.275)
  rrect50% 0.8x2.4 smd: 1(-2.25,-3.775) 2(-0.75,-3.775) 3(0.75,-3.775) 4(2.25,-3.775)
  Top Side keep-out region: -5.552,-4.025 -2.727,-4.025 -2.727,-1.425 -5.552,-1.425
  Top Side keep-out region: -0.91,0.869 0.91,0.869 0.91,3.429 -0.91,3.429
  Top Side keep-out region: -1.9,3.429 -3.9,3.429 -3.9,1.379 -1.9,1.379
  Top Side keep-out region: -1.775,-4.022 -1.225,-4.022 -1.225,-1.422 -1.775,-1.422
  Top Side keep-out region: -0.273,-4.024 0.277,-4.024 0.277,-1.424 -0.273,-1.424
  Top Side keep-out region: 1.225,-4.022 1.775,-4.022 1.775,-1.422 1.225,-1.422
  Top Side keep-out region: 5.55,-1.424 2.725,-1.424 2.725,-4.024 5.55,-4.024
  Top Side keep-out region: 1.9,1.379 3.9,1.379 3.9,3.429 1.9,3.429
  Top Side keep-out lines w0.05: -2.7,-1.449 2.7,-1.449
  body extent -5.15,-4.22 5.15,3.18, height 7.3
MOLEX_5025840760 [mm] "Connector, 1.50mm Pitch, Receptacle, Single Row, SMT, Vertical, 7 Circuits"
  rrect50% 1.65x3.3 smd: 0(-7.025,1.275)
  rrect50% 1.8x3.3 smd: 0(7.1,1.275)
  rrect50% 0.8x2.4 smd: 1(-4.5,-3.775) 2(-3,-3.775) 3(-1.5,-3.775) 4(0,-3.775) 5(1.5,-3.775) 6(3,-3.775) 7(4.5,-3.775)
  Top Side keep-out region: -4.05,-4.013 -3.45,-4.013 -3.45,-1.413 -4.05,-1.413
  Top Side keep-out region: -2.539,-4.024 -1.939,-4.024 -1.939,-1.424 -2.539,-1.424
  Top Side keep-out region: -1.05,-4.035 -0.45,-4.035 -0.45,-1.435 -1.05,-1.435
  Top Side keep-out region: 0.439,-4.024 1.039,-4.024 1.039,-1.424 0.439,-1.424
  Top Side keep-out region: 1.95,-4.013 2.55,-4.013 2.55,-1.413 1.95,-1.413
  Top Side keep-out region: 3.461,-4.024 4.061,-4.024 4.061,-1.424 3.461,-1.424
  Top Side keep-out region: -0.91,0.869 0.91,0.869 0.91,3.429 -0.91,3.429
  Top Side keep-out region: -7.8,-4.024 -4.95,-4.024 -4.95,-1.424 -7.8,-1.424
  Top Side keep-out region: -4.15,3.429 -6.15,3.429 -6.15,1.379 -4.15,1.379
  Top Side keep-out region: 7.8,-1.424 4.95,-1.424 4.95,-4.024 7.8,-4.024
  Top Side keep-out region: 4.15,1.379 6.15,1.379 6.15,3.429 4.15,3.429
  Top Side keep-out lines w0.05: 4.95,-1.449 -4.95,-1.449
  body extent -7.4,-4.22 7.4,3.18, height 7.3
MOLEX_5025840860 [mm] "Connector, 1.50mm Pitch, Receptacle, Single Row, SMT, Vertical, 8 Pins"
  rrect50% 1.8x3.3 smd: 0(-7.85,1.275) 0(7.85,1.275)
  rrect50% 0.8x2.4 smd: 1(-5.25,-3.775) 2(-3.75,-3.775) 3(-2.25,-3.775) 4(-0.75,-3.775) 5(0.75,-3.775) 6(2.25,-3.775) 7(3.75,-3.775) 8(5.25,-3.775)
  Top Side keep-out region: -0.91,0.868 0.91,0.868 0.91,3.428 -0.91,3.428
  Top Side keep-out region: -4.9,3.429 -6.9,3.429 -6.9,1.379 -4.9,1.379
  Top Side keep-out region: -4.801,-4.013 -4.201,-4.013 -4.201,-1.413 -4.801,-1.413
  Top Side keep-out region: -8.55,-4.024 -5.7,-4.024 -5.7,-1.424 -8.55,-1.424
  Top Side keep-out region: -3.289,-4.023 -2.689,-4.023 -2.689,-1.423 -3.289,-1.423
  Top Side keep-out region: -1.801,-4.013 -1.201,-4.013 -1.201,-1.413 -1.801,-1.413
  Top Side keep-out region: -0.289,-4.023 0.311,-4.023 0.311,-1.423 -0.289,-1.423
  Top Side keep-out region: 1.199,-4.013 1.799,-4.013 1.799,-1.413 1.199,-1.413
  Top Side keep-out region: 2.711,-4.023 3.311,-4.023 3.311,-1.423 2.711,-1.423
  Top Side keep-out region: 4.199,-4.013 4.799,-4.013 4.799,-1.413 4.199,-1.413
  Top Side keep-out region: 4.9,1.379 6.9,1.379 6.9,3.429 4.9,3.429
  Top Side keep-out region: 8.55,-1.425 5.7,-1.425 5.7,-4.025 8.55,-4.025
  Top Side keep-out lines w0.05: 5.7,-1.449 -5.7,-1.449
  body extent -8.15,-4.22 8.15,3.18, height 7.3
"MOLEX_ 430450212" [mm] "Micro-Fit 3.0 Vertical Header, 3.00mm Pitch, Dual Row, 2 Circuits, with PCB Polarizing Peg, Black"
  round 0 hole 1.1 unplated mask+0.15: 0(-3,2.44) 0(3,2.44)
  rrect50% 1.8x1.8 hole 1.1: 1(0,-1.5)
  round 1.8 hole 1.1: 2(0,1.5)
  body extent -3.57,-3.94 3.57,4.83, height 9.95
"MOLEX_ 430450612" [mm] "Micro-Fit 3.0 Vertical Header, 3.00mm Pitch, Dual Row, 6 Circuits, with PCB Polarizing Peg, Black"
  round 0 hole 1.1 unplated mask+0.15: 0(-6,2.44) 0(6,2.44)
  rrect50% 1.8x1.8 hole 1.1: 1(3,-1.5)
  round 1.8 hole 1.1: 2(0,-1.5) 3(-3,-1.5) 4(3,1.5) 5(0,1.5) 6(-3,1.5)
  body extent -6.58,-3.97 6.58,4.8, height 9.95
MTGNPH170 [mm] "Mounting Hole, Non-Plated; 0.00 mm Clearance, 1.70 mm Hole"
  round 0 hole 1.7 unplated paste-2539.97 mask+0.15: 1(0,0)
MTGNPH270A550V8H40 [mm] "Mounting Hole, Non-Plated; 5.50 mm Clearance, 2.70 mm Hole (with 8 vias)"
  round 0 hole 2.7 unplated paste-2539.97 mask+2.75: 1(0,0)
  round 0.6 hole 0.4 paste-2539.97 mask-0.6: 2(0,2.2) 3(-1.56,1.56) 4(-2.2,0) 5(-1.56,-1.56) 6(0,-2.2) 7(1.56,-1.56) 8(2.2,0) 9(1.56,1.56)
  Multi-Layer region: -1.65,0 -2.75,0 -2.739,0.24 -2.708,0.477 -2.656,0.712 -2.584,0.941 -2.492,1.162 -2.382,1.375 -2.253,1.577 -2.107,1.768 -1.944,1.944 -1.768,2.107 -1.577,2.253 -1.375,2.382 -1.162,2.492 -0.941,2.584 -0.712,2.656 -0.477,2.708 -0.24,2.739 0,2.75 0.24,2.739 0.477,2.708 0.712,2.656 0.941,2.584 1.162,2.492 1.375,2.382 1.577,2.253 1.768,2.107 1.944,1.944 2.107,1.768 2.253,1.577 2.382,1.375 2.492,1.162 2.584,0.941 2.656,0.712 2.708,0.477 2.739,0.24 2.75,0 2.739,-0.24 2.708,-0.477 2.656,-0.712 2.584,-0.941 2.492,-1.162 2.382,-1.375 2.253,-1.577 2.107,-1.768 1.944,-1.944 1.768,-2.107 1.577,-2.253 1.375,-2.382 1.162,-2.492 0.941,-2.584 0.712,-2.656 0.477,-2.708 0.24,-2.739 0,-2.75 -0.24,-2.739 -0.477,-2.708 -0.712,-2.656 -0.941,-2.584 -1.162,-2.492 -1.375,-2.382 -1.577,-2.253 -1.768,-2.107 -1.944,-1.944 -2.107,-1.768 -2.253,-1.577 -2.382,-1.375 -2.492,-1.162 -2.584,-0.941 -2.656,-0.712 -2.708,-0.477 -2.739,-0.24 -2.75,0 -1.65,0 -1.644,-0.144 -1.625,-0.286 -1.594,-0.427 -1.55,-0.564 -1.495,-0.697 -1.429,-0.825 -1.352,-0.946 -1.264,-1.061 -1.167,-1.167 -1.061,-1.264 -0.946,-1.352 -0.825,-1.429 -0.697,-1.495 -0.564,-1.55 -0.427,-1.594 -0.286,-1.625 -0.144,-1.644 0,-1.65 0.144,-1.644 0.286,-1.625 0.427,-1.594 0.564,-1.55 0.697,-1.495 0.825,-1.429 0.946,-1.352 1.061,-1.264 1.167,-1.167 1.264,-1.061 1.352,-0.946 1.429,-0.825 1.495,-0.697 1.55,-0.564 1.594,-0.427 1.625,-0.286 1.644,-0.144 1.65,0 1.644,0.144 1.625,0.286 1.594,0.427 1.55,0.564 1.495,0.697 1.429,0.825 1.352,0.946 1.264,1.061 1.167,1.167 1.061,1.264 0.946,1.352 0.825,1.429 0.697,1.495 0.564,1.55 0.427,1.594 0.286,1.625 0.144,1.644 0,1.65 -0.144,1.644 -0.286,1.625 -0.427,1.594 -0.564,1.55 -0.697,1.495 -0.825,1.429 -0.946,1.352 -1.061,1.264 -1.167,1.167 -1.264,1.061 -1.352,0.946 -1.429,0.825 -1.495,0.697 -1.55,0.564 -1.594,0.427 -1.625,0.286 -1.644,0.144 -1.65,0
"PANASONIC_AXT410124 (with 3D counterpart)" [mm] "0.40 mm pitch; 10 pin, 3.90 mm L X 1.45 mm W X 1.24 mm H body"
  rrect50% 0.45x0.5 smd: 0(-1.6,-0.575) 0(-1.6,0.575) 0(1.6,-0.575) 0(1.6,0.575)
  rrect50% 0.2x0.77 smd: 1(-0.8,-1.045) 2(-0.8,1.045) 3(-0.4,-1.045) 4(-0.4,1.045) 5(0,-1.045) 6(0,1.045) 7(0.4,-1.045) 8(0.4,1.045) 9(0.8,-1.045) 10(0.8,1.045)
  Top Side keep-out region: -0.983,0.61 0.983,0.61 0.983,0.335 -0.983,0.335
  Top Side keep-out region: -0.983,-0.335 0.983,-0.335 0.983,-0.61 -0.983,-0.61
  body extent -3,-4.55 3,2.7, height 2.5
PANASONIC_F_VIB [mil] "Capacitor, Aluminum Electrolytic; F Panasonic Vibration proof 8.30 mm L X 8.30 mm W X 10.50 mm H Body"
  round 1 smd: 1(-137.8,0) 2(137.8,0)
  Top Side region: 206.69,39.37 214.37,37.65 220.81,33.11 225.03,26.46 226.37,18.7 226.38,18.7 226.38,-18.7 225.03,-26.46 220.81,-33.11 214.37,-37.65 206.69,-39.37 206.69,-39.37 143.7,-39.37 143.7,-79.72 142.72,-84.62 139.95,-88.77 135.8,-91.55 130.9,-92.52 130.9,-92.52 105.31,-92.52 100.42,-91.55 96.26,-88.77 93.49,-84.62 92.52,-79.72 92.52,-79.72 92.52,-39.37 69.88,-39.37 62.12,-38.02 55.47,-33.81 50.93,-27.37 49.21,-19.68 49.21,-19.69 49.21,19.68 52.16,29.71 59.72,36.91 69.88,39.37 69.88,39.37 92.52,39.37 92.52,79.72 93.49,84.62 96.26,88.77 100.42,91.55 105.31,92.52 105.31,92.52 130.9,92.52 135.8,91.55 139.95,88.77 142.72,84.62 143.7,79.72 143.7,79.72 143.7,39.37
  Top Side region: -206.69,-39.37 -214.38,-37.65 -220.82,-33.11 -225.03,-26.46 -226.38,-18.7 -226.38,-18.7 -226.38,18.7 -225.03,26.46 -220.82,33.11 -214.38,37.65 -206.69,39.37 -206.69,39.37 -143.7,39.37 -143.7,79.72 -142.73,84.62 -139.95,88.77 -135.8,91.55 -130.91,92.52 -130.91,92.52 -105.32,92.52 -100.42,91.55 -96.27,88.77 -93.49,84.62 -92.52,79.72 -92.52,79.72 -92.52,39.37 -69.88,39.37 -62.12,38.02 -55.47,33.81 -50.94,27.37 -49.21,19.68 -49.21,19.68 -49.21,-19.69 -50.94,-27.37 -55.47,-33.81 -62.12,-38.02 -69.88,-39.37 -69.88,-39.37 -92.52,-39.37 -92.52,-79.72 -93.49,-84.62 -96.27,-88.77 -100.42,-91.55 -105.32,-92.52 -105.32,-92.52 -130.91,-92.52 -135.8,-91.55 -139.95,-88.77 -142.73,-84.62 -143.7,-79.72 -143.7,-79.72 -143.7,-39.37
  body extent -191,-163 191,163, height 413
RESC100X52X40L22N [mm] "Resistor, Chip; 1.00 mm L X 0.525 mm W X 0.40 mm H body"
  rrect51% 0.59x0.62 smd: 1(-0.47,0) 2(0.47,0)
  body extent -0.55,-0.3 0.55,0.3, height 0.4
RESC200X125X84L35N [mm] "Resistor, Chip; 2.00 mm L X 1.25 mm W X 0.84 mm H body"
  rrect50% 0.96x1.47 smd: 1(-0.925,0) 2(0.925,0)
  body extent -1.1,-0.72 1.1,0.72, height 0.84
RESC320X160X90L47N [mm] "Resistor, Chip; 3.20 mm L X 1.60 mm W X 0.90 mm H body"
  rrect43% 1.15x1.82 smd: 1(-1.48,0) 2(1.48,0)
  body extent -1.7,-0.9 1.7,0.9, height 0.9
SAMTEC_ERM8-025-05.0-L-DV [mm] "0.80 mm Edge Rate® Rugged High Speed Terminal"
  round 1.45 hole 1.45 unplated mask+0.15: 0(-11.4,-1.5) 0(11.4,-1.5)
  rrect50% 0.5x1.1 smd: 1(-9.6,1.9) 2(-9.6,-1.9) 3(-8.8,1.9) 4(-8.8,-1.9) 5(-8,1.9) 6(-8,-1.9) 7(-7.2,1.9) 8(-7.2,-1.9) 9(-6.4,1.9) 10(-6.4,-1.9) 11(-5.6,1.9) 12(-5.6,-1.9) 13(-4.8,1.9) 14(-4.8,-1.9) 15(-4,1.9) 16(-4,-1.9) 17(-3.2,1.9) 18(-3.2,-1.9) 19(-2.4,1.9) 20(-2.4,-1.9) 21(-1.6,1.9) 22(-1.6,-1.9) 23(-0.8,1.9) 24(-0.8,-1.9) 25(0,1.9) 26(0,-1.9) 27(0.8,1.9) 28(0.8,-1.9) 29(1.6,1.9) 30(1.6,-1.9) 31(2.4,1.9) 32(2.4,-1.9) 33(3.2,1.9) 34(3.2,-1.9) 35(4,1.9) 36(4,-1.9) 37(4.8,1.9) 38(4.8,-1.9) 39(5.6,1.9) 40(5.6,-1.9) 41(6.4,1.9) 42(6.4,-1.9) 43(7.2,1.9) 44(7.2,-1.9) 45(8,1.9) 46(8,-1.9) 47(8.8,1.9) 48(8.8,-1.9) 49(9.6,1.9) 50(9.6,-1.9)
  body extent -13,-2.8 13,2.8, height 8.9
SAMTEC_SSM-112-L-DV-A [mil] "Header, 2.54mm Pitch, Dual Row, SMT, Vertical, 24 Circuits"
  round 0 hole 47.24 unplated: 0(-500,0.16) 0(500,0.16)
  rrect50% 40x87.5 smd: 1(550,-111.09) 2(550,111.41) 3(450,-111.09) 4(450,111.41) 5(350,-111.09) 6(350,111.41) 7(250,-111.09) 8(250,111.41) 9(150,-111.09) 10(150,111.41) 11(50,-111.09) 12(50,111.41) 13(-50,-111.09) 14(-50,111.41) 15(-150,-111.09) 16(-150,111.41) 17(-250,-111.09) 18(-250,111.41) 19(-350,-111.09) 20(-350,111.41) 21(-450,-111.09) 22(-450,111.41) 23(-550,-111.09) 24(-550,111.41)
  body extent -600,-138 600,139, height 292
SODFL359X170X143L65X95N [mm] "Diode, Small Outline Diode Flat Lead (SODFL); 2.70 mm L X 1.70 mm W X 1.43 mm H body"
  rrect42% 1.2x1.21 smd: 1(-1.505,0) 2(1.505,0)
  body extent -1.9,-0.95 1.9,0.95, height 1.43
SOIC8P127_490X599X175L83X41N [mm] "Small Outline IC (SOIC), 1.27 mm pitch; 8 pin, 4.90 mm L X 3.90 mm W X 1.75 mm H body"
  rrect52% 0.66x2.07 smd: 1(-1.905,-2.42) 2(-0.635,-2.42) 3(0.635,-2.42) 4(1.905,-2.42) 5(1.905,2.42) 6(0.635,2.42) 7(-0.635,2.42) 8(-1.905,2.42)
  body extent -2.5,-3.1 2.5,3.1, height 1.75
SOIC16P127_1139X671X151L61X41N [mm] "DIP8-SMD-Small, 1.27 mm pitch; 16 pin, 11.39 mm L X 4.50 mm W X 1.51 mm H Body"
  rrect50% 0.634x1.501 smd: 1(-4.445,-3.007) 2(-3.175,-3.007) 3(-1.905,-3.007) 4(-0.635,-3.007) 5(0.635,-3.007) 6(1.905,-3.007) 7(3.175,-3.007) 8(4.445,-3.007) 9(4.445,3.007) 10(3.175,3.007) 11(1.905,3.007) 12(0.635,3.007) 13(-0.635,3.007) 14(-1.905,3.007) 15(-3.175,3.007) 16(-4.445,3.007)
  body extent -5.69,-3.35 5.7,3.35, height 1.55
SOT23-5P65_210X110L28X20N [mm] "Small Outline Transistor (SOT23), 0.65 mm pitch; 5 pin, 2.025 mm L X 1.25 mm W X 1.10 mm H body"
  rrect49% 0.37x1.04 smd: 1(-0.65,-0.935) 2(0,-0.935) 3(0.65,-0.935) 4(0.65,0.935) 5(-0.65,0.935)
  body extent -1.12,-1.2 1.12,1.2, height 1.1
Steg_570X90_7Hole [mm] "Steg; 5.70 mm L X 0.90 mm W, 7 Hole, Bear-Ears, Preferred"
  round 0 hole 0.35 unplated mask+0.15: 0(-1.5,0) 0(-1,0) 0(-0.5,0) 0(0,0) 0(0.5,0) 0(1,0) 0(1.5,0)
  Keep-Out Layer lines w0.05: 2.825,0 ccw(c1.8,-0.4) 1.8,0.7 -1.8,0.7 ccw(c-1.8,-0.4) -2.825,0
TESTPOINT_c120 [mm] "Test Point; 1 pin, 1.20 mm D X 0.00 mm H body"
  round 1.2 smd paste-2: 1(0,0)
  body extent -0.6,-0.6 0.6,0.6, height 0.01
TESTPOINTMEASURE_c50 [mm] "Test Point Measure; 1 pin, 0.50 mm D X 0.00 mm H body"
  round 0.5 smd paste-2: 1(0,0)
  body extent -0.25,-0.25 0.25,0.25, height 0.01
"UL_MANUFACTURER _MARKING_PCB_880x170" [mm] "UL Marking PCB, 8.80 mm L X 1.70 mm W X 0.00 mm H body"
  Top Side keep-out region: -4.4,0.85 4.4,0.85 4.4,-0.85 -4.4,-0.85
  body extent -4.4,-0.85 4.4,0.85, height 0.02

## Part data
C101 C102 C103 C104: library part CMP-000967-5, "Polymer Hybrid Elco 22uF >=80V 20% D=8mm, H=10.5mm", Case="G, D{}8mm, H{}10.5mm", Manufacturer=Panasonic, Max Operating Temperature=105°C, Maximum Working Voltage=80V, Min Operating Temperature=-55°C, Ripple Current=1.55A, Tolerance=20%
C106 C108: library part CMP-000937-4, "10nF X7R >=630V 20%", Case=0805, Case (Metric)=2012, Dielectric=X7R, Dielectric Withstanding Voltage="> 850V 1sec", Manufacturer=Murata, Max Operating Temperature=125°C, Maximum Working Voltage=630V, Min Operating Temperature=-55°C, Tolerance=20%
C107 C109 C111: library part CMP-001011-3, "470p C0G/NP0/X7R >=100V 20%", Case=0603, Case (Metric)=1608, Dielectric=C0G/NP0/X7R, Manufacturer=X, Max Operating Temperature=125°C, Maximum Working Voltage=100V, Min Operating Temperature=-55°C, Part Number="Ceramic, 0603, 470pF, 20%, >{}100V, C0G/NP0/X7R, @, Soft Termination: N, -55°C to 125°C", Tolerance=20%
